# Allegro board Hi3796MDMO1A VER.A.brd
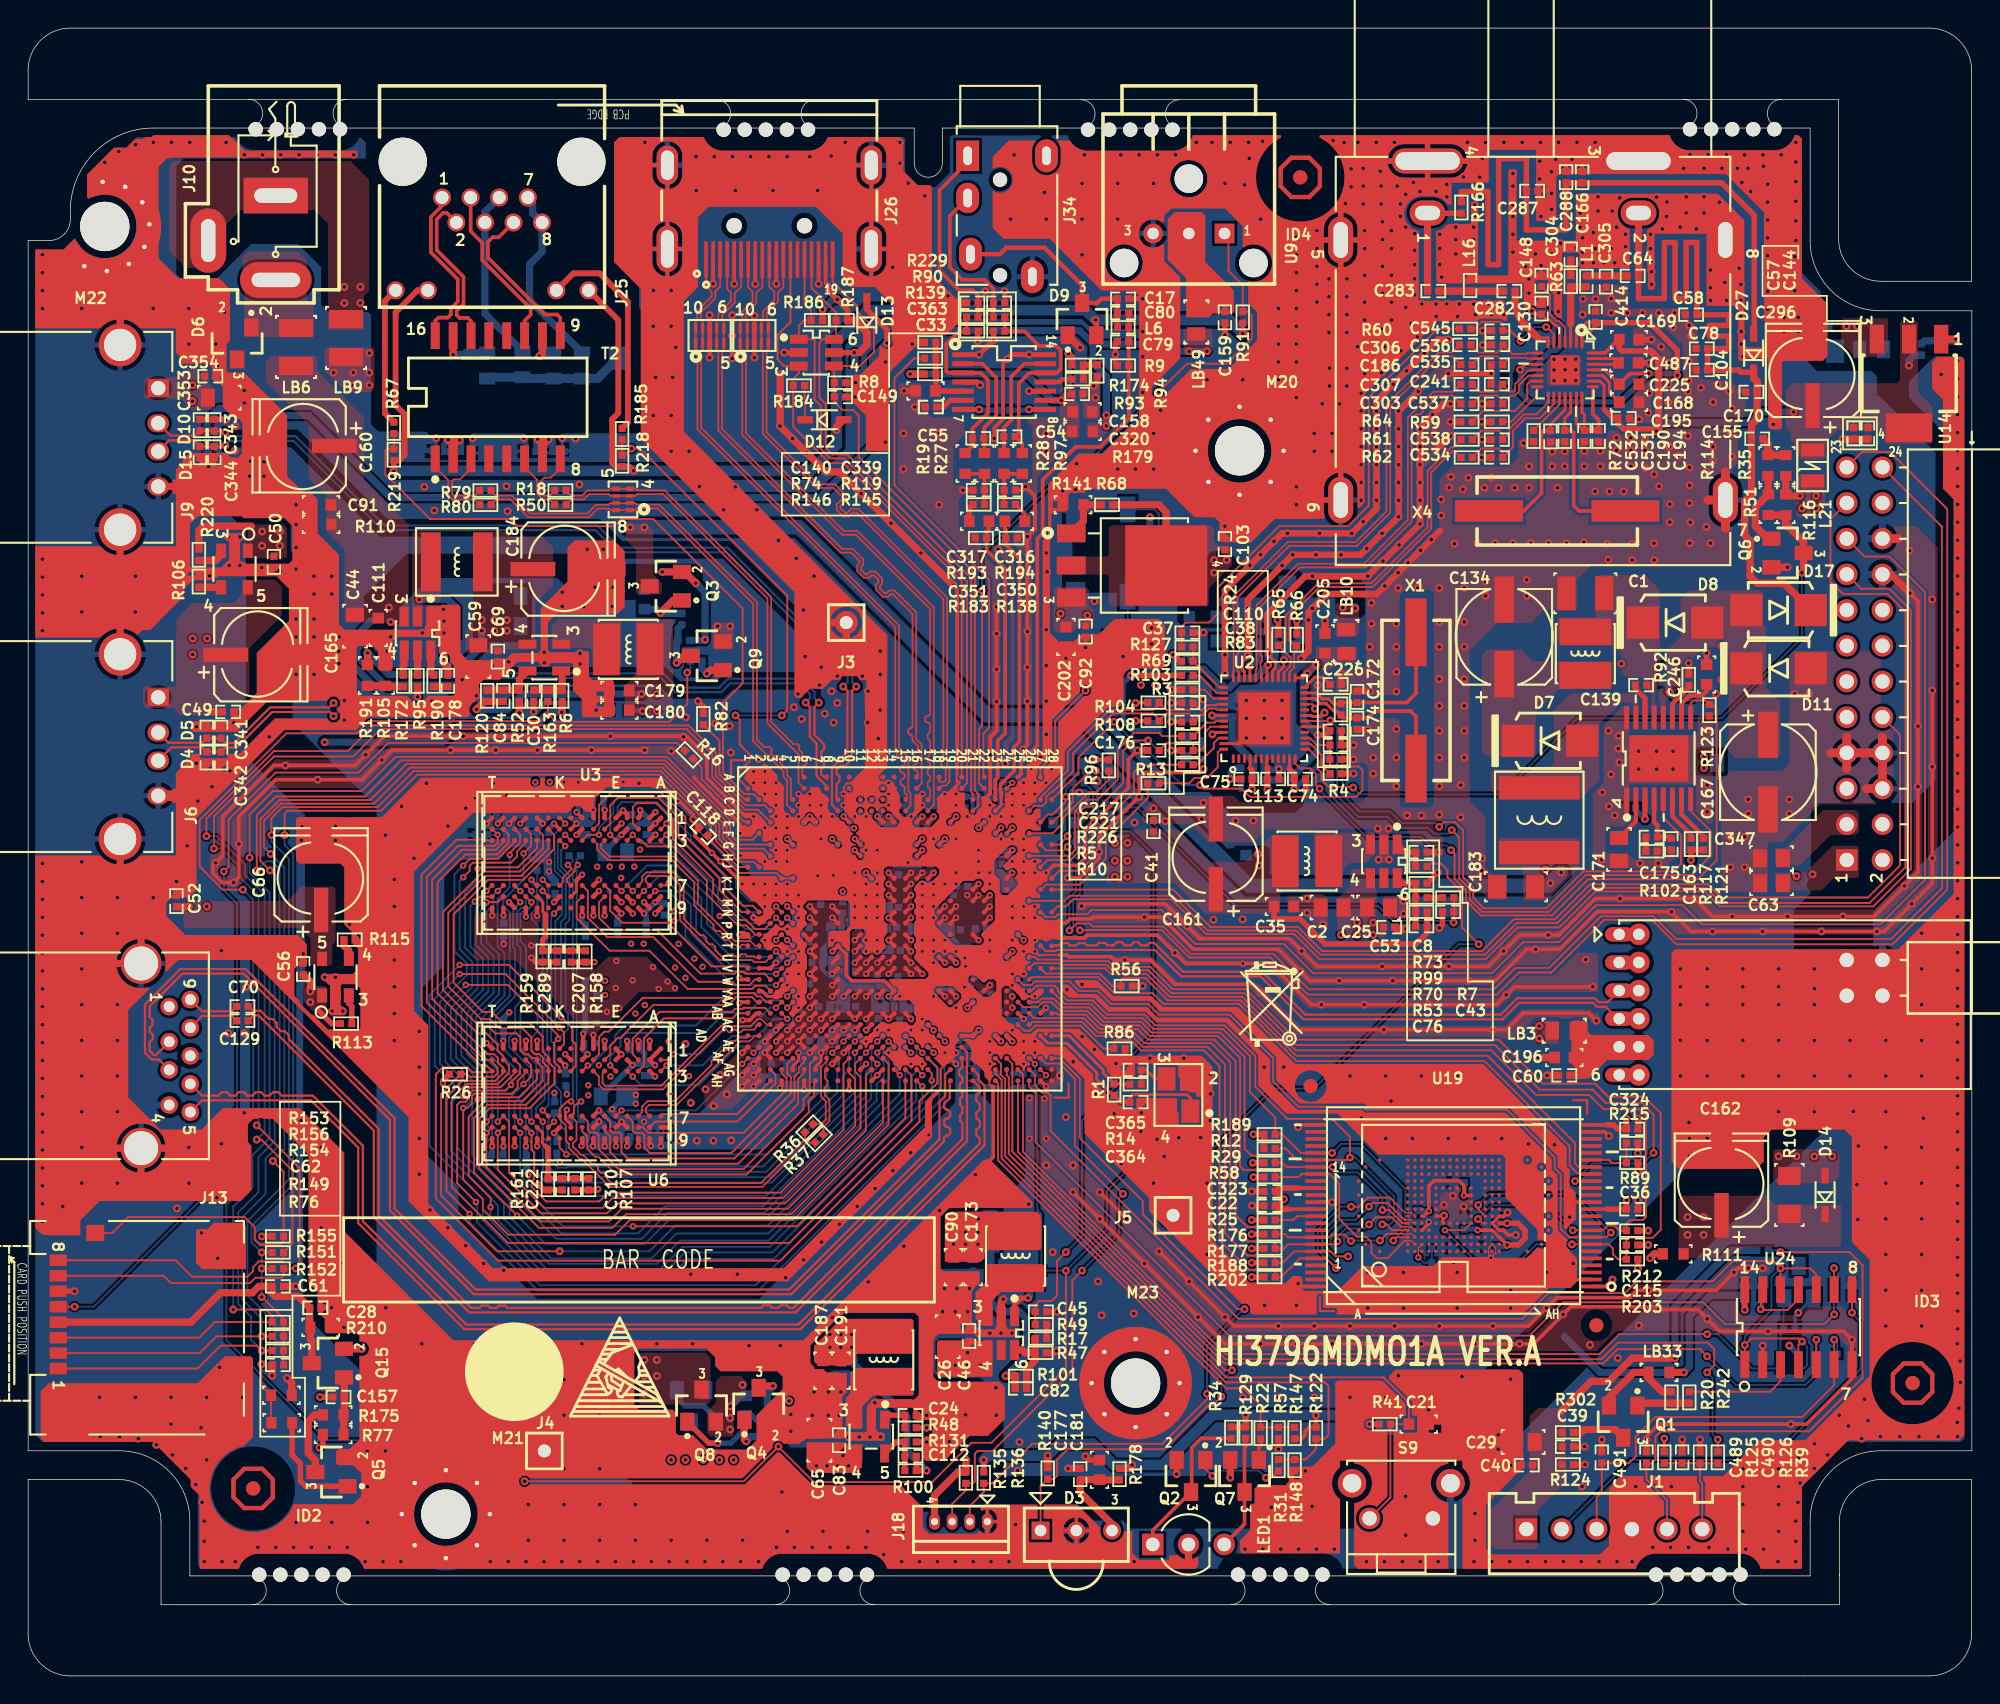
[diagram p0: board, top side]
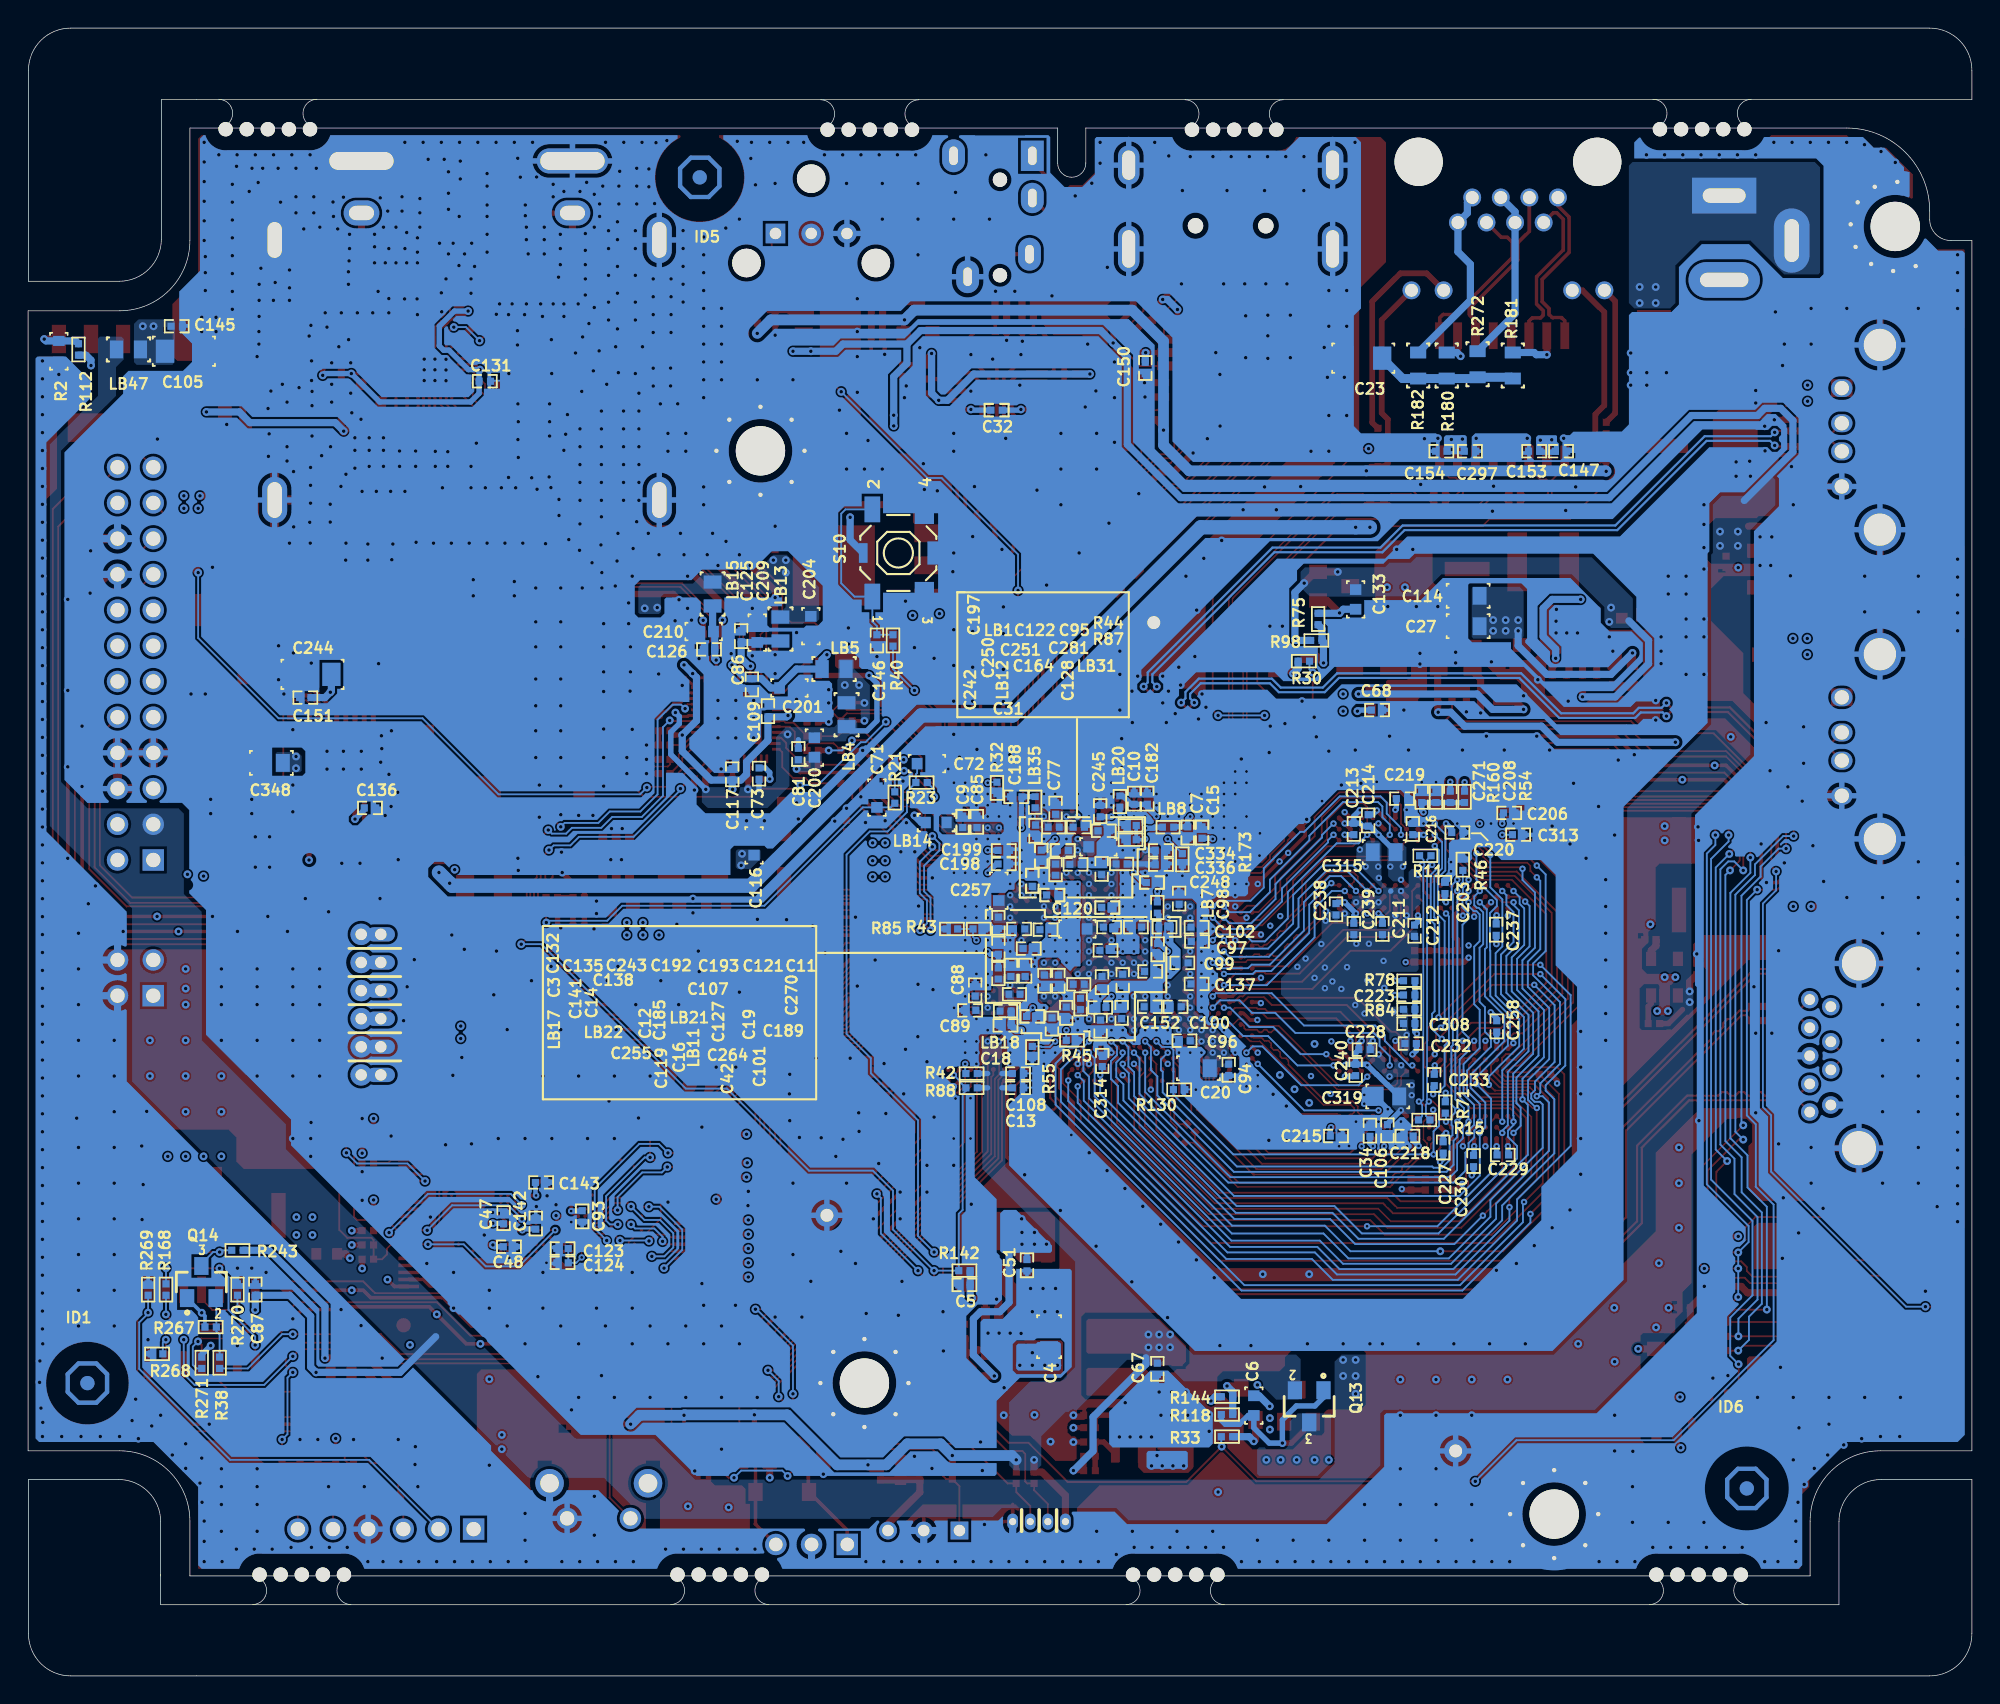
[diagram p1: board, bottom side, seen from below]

Outline 138.2 x 117.22 mm; copper layers: TOP, GND02, POWER03, BOTTOM. Coordinates in mm from the lower left corner of the outline.
Outline path: 128.78,7.11 128.78,10.97 arc(129.66,13.09) 131.78,13.97 138.18,13.97 138.18,3 arc(137.3,0.88) 135.18,0 3,0 arc(0.88,0.88) 0,3 0,13.97 6.45,13.97 arc(8.57,13.09) 9.45,10.97 9.45,5.06 128.78,5.06 128.78,7.24 ; 0,114.22 arc(0.88,116.34) 3,117.22 135.18,117.22 arc(137.3,116.34) 138.18,114.22 138.18,99.21 131.72,99.21 arc(129.61,100.09) 128.73,102.21 128.73,112.14 0,112.14 0,114.22 ; 0,102.11 0,16.01 6.5,16.01 arc(10.04,14.55) 11.5,11.01 11.5,7.11 126.7,7.11 126.7,11.01 arc(128.16,14.55) 131.7,16.01 138.2,16.01 138.2,97.11 131.7,97.11 arc(128.16,98.58) 126.7,102.11 126.7,110.11 65,110.11 65,107.61 arc(64,106.61) 63,107.61 63,110.11 8.9,110.11 arc(4.73,108.38) 3,104.21 3,103.61 arc(2.56,102.55) 1.5,102.11 0,102.11

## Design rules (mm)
constraint set DEFAULT: min track width 0.127
net group $7N2063: nets $7N2063 USB_BOOT
net group $8N1816: nets $8N1816 DDR_CLK1P
net group $8N1817: nets $8N1817 DDR_CLK1N
net group $22N979: nets $22N979 SIM0_DET
net group $22N1011: nets $22N1011 SIM0_DATA
net group DIFFPAIR8: nets DDR_DQS0N DDR_DQS0P
net group DIFFPAIR9: nets DDR_DQS1N DDR_DQS1P
net group DIFFPAIR10: nets DDR_DQS2N DDR_DQS2P
net group DIFFPAIR11: nets DDR_DQS3N DDR_DQS3P
net group DIFFPAIR21: nets $17N178 $17N179
net group DIFFPAIR22: nets $17N175 $17N176
net group DIFFPAIR24: nets USB3_TXN USB3_TXP
net group DIFFPAIR25: nets 3136_QOUT_N 3136_QOUT_P
net group DIFFPAIR26: nets 3136_IOUT_N 3136_IOUT_P
net group DIFFPAIR28: nets $21N333 $21N334
net group DIFFPAIR29: nets $21N336 $21N337
net group DIFFPAIR30: nets $17N281 $17N285
net group DIFFPAIR31: nets $17N276 $17N279
net group 01: nets MUTE_CTRL
net group 02: nets STANDBY_PWROFF
net group $5N541: nets $5N541
net group $5N592: nets $5N592
net group $15N771: nets $15N771 IR_IN UART0_RXD UART0_TXD
net group DDR: nets DDR_ADDR0 DDR_ADDR1 DDR_ADDR2 DDR_ADDR3 DDR_ADDR4 DDR_ADDR5 DDR_ADDR6 DDR_ADDR7 DDR_ADDR8 DDR_ADDR9 DDR_ADDR10 DDR_ADDR11 DDR_ADDR12 DDR_ADDR13 DDR_ADDR14 DDR_ADDR15 DDR_BA0 DDR_BA1 DDR_BA2 DDR_CASN DDR_CKE DDR_CSN DDR_DM0 DDR_DM1 DDR_DM2 DDR_DM3 DDR_DQ0 DDR_DQ1 DDR_DQ2 DDR_DQ3 DDR_DQ4 DDR_DQ5 DDR_DQ6 DDR_DQ7 DDR_DQ8 DDR_DQ9 DDR_DQ10 DDR_DQ11 DDR_DQ12 DDR_DQ13 DDR_DQ14 DDR_DQ15 DDR_DQ16 DDR_DQ17 DDR_DQ18 DDR_DQ19 DDR_DQ20 DDR_DQ21 DDR_DQ22 DDR_DQ23 DDR_DQ24 DDR_DQ25 DDR_DQ26 DDR_DQ27 DDR_DQ28 DDR_DQ29 DDR_DQ30 DDR_DQ31 DDR_ODT DDR_RASN DDR_RESETN DDR_WEN
net group DIFF90: nets USB0_DM USB0_DP USB1_DM USB1_DP
net group PHY: nets RX+_PHY0 RX-_PHY0 TX+_PHY0 TX-_PHY0
net group POWER: nets 1V2_DVDD_S 12V0_MOS ADAC_VOUTL ADAC_VOUTR CVBS
net group USB: nets $14N652 $14N653 USB2_DM USB2_DP USB3_DM USB3_DP USB3_RXN USB3_RXP

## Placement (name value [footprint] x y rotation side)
C1  4.7UF  [SC1210]  110.72 77.01 180 top
C2  10UF  [SC0805]  92.71 54.66 180 top
C3  1UF  [SC0402]  69.22 51.74 90 bottom
C4  10UF  [SC0805]  65.61 24.13 90 bottom
C5  220NF  [SC0402]  71.63 27.81 0 bottom
C6  220NF  [SC0603]  51.05 19.23 270 bottom
C7  1UF  [SC0402]  55.75 59.99 270 bottom
C8  220NF  [SC0402]  99.06 58.6 0 top
C9  2.2UF  [HSC0402]  71.75 60.76 90 bottom
C10  1UF  [SC0402]  59.56 62.41 90 bottom
C11  1UF  [SC0402]  57.4 53.26 180 bottom
C12  1UF  [SC0402]  65.94 49.45 270 bottom
C13  1UF  [SC0402]  67.82 41.83 180 bottom
C14  1UF  [SC0402]  67.31 50.16 90 bottom
C15  2.2UF  [HSC0402]  54.74 59.99 90 bottom
C16  1UF  [SC0402]  64.39 47.17 270 bottom
C17  180PF  [SC0402]  77.85 97.97 0 top
C18  1UF  [SC0402]  68.71 46.28 0 bottom
C19  470NF  [SC0402]  60.38 49.5 270 bottom
C20  10UF  [SC0805]  54.99 43.23 0 bottom
C21  100NF  [SC0603]  98.87 17.91 0 top
C22  2.2UF  [HSC0402]  88.27 33.45 180 top
C23  1NF  [SC1206]  43.27 93.74 0 bottom
C24  220NF  [SC0402]  62.74 18.54 0 top
C25  10UF  [SC0805]  96.01 54.66 0 top
C26  10UF/NC  [SC0805]  65.38 24.13 90 top
C27  10UF/NC  [SC0805]  35.81 74.68 0 bottom
C28  2.2UF  [HSC0402]  20.42 26.19 0 top
C29  10UF  [SC0805]  106.3 16.64 180 top
C30  220NF  [SC0402]  35.94 69.72 270 top
C31  2.2UF  [HSC0402]  65.38 55.55 180 bottom
C32  330N  [HSC0402]  69.34 90.04 0 bottom
C33  330N  [HSC0402]  64.19 90.27 0 top
C34  100NF  [SC0402]  42.8 38.79 90 bottom
C35  10UF  [SC0603]  89.28 54.74 0 top
C36  1UF/NC  [SC0402]  114.05 33.2 0 top
C37  100NF  [SC0402]  82.42 74.22 0 top
C38  100NF  [SC0402]  92.96 66.22 0 top
C39  100NF  [SC0402]  109.47 16.31 0 top
C40  100NF  [SC0402]  106.55 14.99 180 top
C41  100NF  [SC0402]  80.01 60.45 90 top
C42  100NF  [SC0402]  61.95 46.25 270 bottom
C43  100NF/NC  [SC0402]  100.97 54.36 180 top
C44  10UF  [SC0805]  23.24 74.68 270 top
C45  100NF/NC  [SC0402]  72.01 25.91 0 top
C46  100NF  [SC0402]  66.9 24.18 90 top
C47  100NF  [SC0402]  104.39 32.56 90 bottom
C48  100NF  [SC0402]  104.01 30.53 180 bottom
C49  100NF  [SC0402]  14.22 68.58 0 top
C50  100NF  [SC0402]  17.48 79.25 270 top
C51  100NF  [SC0402]  67.18 29.21 270 bottom
C52  100NF  [SC0402]  10.54 55.12 90 top
C53  100NF  [SC0402]  96.77 53.26 0 top
C54  47PF  [SC0402]  69.77 88.16 180 top
C55  47PF  [SC0402]  67.55 88.04 180 top
C56  100NF  [SC0402]  19.56 50.29 90 top
C57  10NF  [HSC0402]  129.79 88.39 270 top
C58  39PF/NC  [SC0402]  118.24 96.84 180 top
C59  10UF  [SC0805]  32 72.52 270 top
C60  100NF  [SC0402]  109.22 42.72 180 top
C61  100NF  [SC0402]  17.75 27.71 0 top
C62  100NF  [SC0402]  17.75 22.12 180 top
C63  10UF  [SC0805]  123.95 56.39 180 top
C64  39PF  [SC0402]  114.09 99.59 180 top
C65  10UF  [SC0805]  56.26 16.76 90 top
C66  100UF  [SAC6666]  20.83 56.98 90 top
C67  100NF  [SC0402]  57.91 21.84 270 bottom
C68  100NF  [SC0402]  42.29 68.71 180 bottom
C69  100NF  [SC0402]  33.4 72.52 270 top
C70  100NF  [SC0402]  15.24 47.62 0 top
C71  2.2UF  [SC0603]  77.85 62.48 90 bottom
C72  2.2UF  [SC0603]  74.3 64.9 180 bottom
C73  100NF  [SC0402]  86.23 64.19 90 bottom
C74  100NF  [SC0402]  90.42 63.8 0 top
C75  100NF  [SC0402]  86.61 63.8 180 top
C76  22PF  [SC0402]  99.06 53.34 0 top
C77  1UF  [SC0402]  65.15 61.7 90 bottom
C78  39PF  [SC0402]  119 94.42 180 top
C79  180PF  [SC0402]  77.85 94.92 180 top
C80  100PF  [SC0402]  77.85 96.95 180 top
C81  100NF  [SC0402]  83.44 65.58 270 bottom
C82  22PF  [SC0402]  70.59 20.45 180 top
C83  100NF  [SC0402]  57.66 16.76 90 top
C84  22PF  [SC0402]  33.78 69.72 270 top
C85  100NF  [SC0402]  70.74 60.76 90 bottom
C86  100NF  [SC0402]  86.74 70.54 270 bottom
C87  100NF  [SC0402]  122.05 27.48 270 bottom
C88  100NF  [SC0402]  70.87 48.77 90 bottom
C89  100NF  [SC0402]  71.22 47.35 0 bottom
C90  10UF  [SC0603]  65.79 29.08 270 top
C91  100NF  [SC0603]  20.83 83.31 180 top
C92  100NF  [SC0402]  75.18 74.3 270 top
C93  100NF  [SC0402]  98.81 32.69 270 bottom
C94  1UF  [SC0402]  52.84 43.12 270 bottom
C95  100NF  [SC0402]  61.72 60.12 180 bottom
C96  1UF  [SC0402]  55.98 45.19 0 bottom
C97  470NF  [SC0402]  55.09 52.25 180 bottom
C98  100NF  [SC0402]  56.36 55.3 90 bottom
C99  100NF  [SC0402]  56.13 50.72 0 bottom
C100  470NF  [SC0402]  56.62 47.6 0 bottom
C101  100NF  [SC0402]  60.45 47.17 90 bottom
C102  100NF  [SC0402]  55.12 53.26 180 bottom
C103  100NF  [SC0402]  85.09 80.52 90 top
C104  39PF/NC  [SC0402]  119 92.9 180 top
C105  10UF  [SC1206]  127.13 94.23 180 bottom
C106  100NF  [SC0402]  41.55 38.81 270 bottom
C107  100NF  [SC0402]  61.59 51.61 180 bottom
C108  100NF  [SC0402]  67.82 42.85 180 bottom
C109  100NF  [SC0402]  85.6 68.63 90 bottom
C110  100NF  [SC0402]  92.96 67.23 0 top
C111  100NF  [SC0603]  24.89 74.55 270 top
C112  22PF  [SC0402]  62.74 15.62 0 top
C113  100NF  [SC0402]  88.52 63.8 0 top
C114  10UF  [SC0805]  35.81 76.83 0 bottom
C115  1NF/NC  [SC0402]  114.05 30.66 0 top
C116  10UF  [SC0603]  86.59 59.08 90 bottom
C117  100NF  [SC0402]  88.14 64.14 90 bottom
C118  2.2UF  [HSC0402]  48.01 60.07 315 top
C119  100NF  [SC0402]  65.41 46.41 270 bottom
C120  2.2UF  [HSC0402]  61.47 54.66 180 bottom
C121  100NF  [SC0402]  59.44 53.26 0 bottom
C122  100NF  [SC0402]  63.5 60.38 180 bottom
C123  100NF  [SC0402]  100.2 30.4 0 bottom
C124  100NF  [SC0402]  100.2 29.39 0 bottom
C125  100NF  [SC0402]  87.5 73.96 90 bottom
C126  100NF  [SC0402]  89.79 73.02 0 bottom
C127  100NF  [SC0402]  61.85 49.35 270 bottom
C128  100NF  [SC0402]  61.87 57.4 90 bottom
C129  100NF  [SC0402]  15.24 46.61 0 top
C130  100NF/NC  [SC0402]  107.6 97.27 90 top
C131  100NF  [SC0402]  105.73 92.1 180 bottom
C132  1UF  [SC0402]  69.22 53.57 270 bottom
C133  1UF  [SC0603]  43.81 76.58 270 bottom
C134  47UF  [SCAPC2-0606]  104.95 73.91 90 top
C135  100NF  [SC0402]  67.74 53.14 0 bottom
C136  100NF  [SC0402]  113.89 61.75 180 bottom
C137  100NF  [SC0402]  55.12 49.23 180 bottom
C138  100NF  [SC0402]  67.06 51.74 180 bottom
C139  100NF  [SC0402]  114.68 70.48 0 top
C140  1NF  [SC0402]  67.13 97.68 180 top
C141  10NF  [SC0402]  68.33 50.16 90 bottom
C142  100NF/NC  [SC0402]  102.11 32.18 90 bottom
C143  100NF/NC  [SC0402]  101.73 35.1 180 bottom
C144  100NF  [SC0402]  130.81 88.39 270 top
C145  100NF  [SC0402]  127.64 96.01 180 bottom
C146  100NF  [SC0402]  77.85 73.66 270 bottom
C147  10NF/NC  [SC0402]  29.21 87.12 180 bottom
C148  22PF  [SC0402]  107.6 99.25 90 top
C149  100NF  [SC0402]  57.73 90.98 0 top
C150  100NF  [SC0402]  58.77 93.04 270 bottom
C151  100NF  [SC0402]  118.49 69.6 0 bottom
C152  1UF  [SC0402]  58.45 47.6 180 bottom
C153  100NF  [SC0402]  31.11 87.12 0 bottom
C154  100NF  [SC0402]  37.72 87.12 0 bottom
C155  100NF  [SC0402]  122.94 88.01 180 top
C157  1UF  [SC0402]  22.07 19.84 0 top
C158  100NF  [SC0402]  74.59 91.2 0 top
C159  100NF  [SC0402]  85.09 96.65 270 top
C160  100UF  [SAC6666]  19.27 87.5 180 top
C161  100UF  [SAC6666]  84.45 58.46 90 top
C162  100UF/NC  [SAC6666]  120.4 35.27 90 top
C163  470PF  [SC0402]  116.83 59.17 90 top
C164  10NF  [SC0402]  63.73 57.73 180 bottom
C165  100UF  [SAC6666]  16.55 72.64 0 top
C166  1NF  [SC0402]  110.49 106.62 90 top
C167  47UF/NC  [SCAPC2-0606]  123.7 64.29 270 top
C168  1NF  [SC0603]  113.82 90.62 180 top
C169  1NF/NC  [SC0603]  113.82 95.06 180 top
C170  1NF  [SC0402]  122.53 91.34 180 top
C171  220NF  [SC0805]  113.12 58.79 90 top
C172  30PF  [SC0402]  94.49 69.65 90 top
C173  10UF  [SC0603]  67.18 29.08 270 top
C174  30PF  [SC0402]  94.49 67.74 270 top
C175  47NF  [SC0402]  115.43 59.68 0 top
C176  1PF/NC  [SC0402]  80.01 65.84 180 top
C177  100NF  [SC0402]  74.8 14.35 90 top
C178  1UF  [SC0402]  29.84 70.79 90 top
C179  10UF  [SC0603]  42.04 70.1 180 top
C180  10UF  [SC0603]  42.04 68.71 180 top
C181  10UF  [SC0603]  76.17 14.66 90 top
C182  10NF  [SC0402]  58.62 62.41 90 bottom
C183  10UF  [SC1206]  105.79 56.13 180 top
C184  100UF  [SAC6666]  38.39 78.74 0 top
C185  10NF  [SC0402]  64.95 49.45 270 bottom
C186  100NF  [SC0402]  102.27 93.28 180 top
C187  10UF  [SC0603]  56.52 21.72 270 top
C188  1UF  [SC0402]  67.94 62.53 0 bottom
C189  1UF  [SC0402]  58.42 50.11 180 bottom
C190  100NF/NC  [SC0402]  110.65 88.2 270 top
C191  10UF  [SC0603]  57.78 21.72 270 top
C192  10UF  [SC0603]  63.6 53.14 0 bottom
C193  1UF  [SC0402]  61.34 53.26 180 bottom
C194  100NF  [SC0402]  111.67 88.2 270 top
C195  100NF  [SC0402]  113.44 89.47 180 top
C196  10UF  [SC0603]  109.22 43.99 180 top
C197  100NF  [SC0402]  66.57 60.12 270 bottom
C198  100NF  [SC0402]  68.83 57.76 180 bottom
C199  100NF  [SC0402]  68.83 58.72 180 bottom
C200  10UF  [SC0603]  82.3 66.04 270 bottom
C201  10UF  [SC0603]  84.07 70.28 180 bottom
C202  10UF  [SC0603]  73.79 73.91 270 top
C203  100NF  [SC0402]  37.47 56.06 90 bottom
C204  10UF  [SC0603]  82.55 74.68 270 bottom
C205  10UF  [SC0603]  92.2 73.46 90 top
C206  100NF  [SC0402]  32.89 61.39 180 bottom
C207  100NF  [SC0402]  38.61 51.18 90 top
C208  100NF  [SC0402]  37.08 62.53 270 bottom
C209  10UF  [SC0603]  86.36 74.22 90 bottom
C210  10UF  [SC0603]  90.17 74.3 0 bottom
C211  100NF  [SC0402]  41.91 53.14 270 bottom
C212  100NF  [SC0402]  39.62 53.01 270 bottom
C213  100NF  [SC0402]  43.94 60.25 270 bottom
C214  100NF  [SC0402]  42.92 60.86 90 bottom
C215  100NF  [SC0402]  45.21 38.4 180 bottom
C216  100NF  [SC0402]  39.75 60.25 90 bottom
C217  33PF/NC  [SC0402]  82.42 69.22 180 top
C218  100NF  [SC0402]  40.13 38.4 0 bottom
C219  100NF  [SC0402]  40.51 62.41 180 bottom
C220  100NF  [SC0402]  36.58 59.99 180 bottom
C221  33PF/NC  [SC0402]  82.42 67.87 180 top
C222  100NF  [SC0402]  37.97 34.98 90 top
C223  100NF  [SC0402]  40.01 48.44 180 bottom
C225  1NF/NC  [SC0603]  113.82 91.89 180 top
C226  10PF  [SC0402]  92.96 70.54 0 top
C227  100NF  [SC0402]  37.59 37.59 270 bottom
C228  100NF  [SC0402]  43.18 44.55 180 bottom
C229  100NF  [SC0402]  33.35 37.06 180 bottom
C230  100NF  [SC0402]  35.43 36.63 270 bottom
C232  100NF  [SC0402]  39.9 44.98 0 bottom
C233  100NF  [SC0402]  38.23 42.39 270 bottom
C237  100NF  [SC0402]  33.82 53.09 270 bottom
C238  100NF  [SC0402]  45.21 54.53 270 bottom
C239  100NF  [SC0402]  43.94 53.14 270 bottom
C240  100NF  [SC0402]  43.81 43.1 270 bottom
C241  10PF  [SC0402]  104.43 91.89 180 top
C242  2.2UF  [HSC0402]  66.8 56.57 90 bottom
C243  470NF  [SC0402]  65.86 53.09 180 bottom
C244  1UF/NC  [SC1206]  117.98 71.25 0 bottom
C245  100NF  [SC0402]  61.98 61.52 90 bottom
C246  22NF  [SC0603]  119.34 71.24 90 top
C248  2.2UF  [HSC0402]  58.29 56.44 180 bottom
C250  2.2UF  [HSC0402]  66.17 58.34 90 bottom
C251  2.2UF  [HSC0402]  64.64 58.72 0 bottom
C255  2.2UF  [HSC0402]  66.8 46.91 0 bottom
C257  10UF  [SC0603]  69.19 55.85 90 bottom
C258  100NF  [SC0402]  33.78 46.2 90 bottom
C264  10NF  [SC0402]  61.98 47.55 0 bottom
C270  10NF  [SC0402]  57.89 51.69 270 bottom
C271  1UF  [SC0402]  39.12 62.53 90 bottom
C281  10UF  [SC0603]  62.1 58.98 180 bottom
C282  47PF  [SC0402]  105.32 98.51 0 top
C283  47PF  [SC0402]  99.9 98.51 0 top
C287  2.2NF  [SC0402]  106.93 105.64 0 top
C288  1NF  [SC0402]  109.35 106.62 90 top
C289  1UF  [SC0402]  37.59 51.18 270 top
C296  220UF  [SAC6666]  126.87 92.87 90 top
C297  10NF/NC  [SC0402]  35.69 87.12 180 bottom
C303  100NF  [SC0402]  102.27 90.49 180 top
C304  100NF/NC  [SC0402]  109.68 101.12 270 top
C305  100NF/NC  [SC0402]  112.19 99.19 90 top
C306  100NF  [SC0402]  102.17 94.68 180 top
C307  100NF  [SC0402]  102.27 91.89 180 top
C308  1UF  [SC0402]  40.01 46.41 0 bottom
C310  1UF  [SC0402]  38.86 34.98 270 top
C313  1NF  [SC0402]  32.26 59.84 180 bottom
C314  1NF  [SC0402]  61.83 43.75 90 bottom
C315  10UF  [SC0805]  41.78 58.6 0 bottom
C316  680PF  [SC0402]  69.8 84.35 0 top
C317  680PF  [SC0402]  67.59 84.35 180 top
C319  10UF  [SC0805]  41.53 41.22 0 bottom
C320  10UF  [SC0603]  74.97 89.93 0 top
C323  100NF  [SC0402]  88.27 34.47 180 top
C324  100NF  [SC0402]  114.05 38.91 0 top
C334  1UF  [SC0402]  57.66 58.72 180 bottom
C336  10NF  [SC0402]  57.66 57.71 180 bottom
C339  1NF  [SC0402]  69.04 97.68 0 top
C341  3PF  [SC0402]  13.72 67.11 270 top
C342  3PF  [SC0402]  13.72 65.33 90 top
C343  3PF  [SC0402]  13.23 88.98 270 top
C344  3PF  [SC0402]  13.23 87.05 90 top
C347  10UF  [SC0805]  123.95 58.17 180 top
C348  10UF  [SC0805]  120.9 64.95 0 bottom
C350  2.2UF  [SC0603]  70.15 82.14 180 top
C351  2.2UF  [SC0603]  67.61 82.14 180 top
C353  10UF  [SC0805]  13.59 90.93 0 top
C354  100NF  [SC0402]  12.95 92.46 0 top
C363  10UF/NC  [SC0603]  63.8 91.41 180 top
C364  30PF  [SC0402]  78.74 40.82 0 top
C365  30PF  [SC0402]  78.74 43.1 180 top
C414  10NF  [SC0402]  111.45 96.67 90 top
C487  1UF  [SC0603]  113.77 93.41 180 top
C489  100PF  [SC0402]  115.06 15.54 90 top
C490  100PF  [SC0402]  117.6 15.54 90 top
C491  100PF  [SC0402]  111.89 15.54 90 top
C531  27PF  [SC0402]  109.25 88.2 270 top
C532  27PF  [SC0402]  108.24 88.18 270 top
C534  10PF  [SC0402]  104.43 86.68 180 top
C535  10PF  [SC0402]  104.43 93.28 180 top
C536  10PF  [SC0402]  104.46 94.68 180 top
C537  10PF  [SC0402]  104.43 90.49 180 top
C538  10PF  [SC0402]  104.43 87.95 180 top
C545  100PF  [SC0402]  104.46 95.7 180 top
D3  IR  [SEN3-100C]  74.52 10.34 0 top
D4  NC  [SC0402]  12.7 65.33 270 top
D5  NC  [SC0402]  12.7 67.11 90 top
D6  D2-3_D  [SOT23]  14.86 94.79 180 top
D7  DIODE  [SD1714A]  108.2 66.52 180 top
D8  DIODE  [SD1714A]  117.09 74.93 180 top
D9  D2-3_A  [SOT23]  74.93 96.52 0 top
D10  NC  [SC0402]  12.22 88.98 90 top
D11  DIODE  [SD1714A]  124.46 71.68 180 top
D12  D_A  [HSOD323A]  56.61 89.36 180 top
D13  D_A  [HSOD323A]  59.63 96.44 270 top
D14  NC  [HSOD323A]  127.76 34.21 270 top
D15  NC  [SC0402]  12.22 87.05 270 top
D17  DIODE  [SD1714A]  124.46 75.82 0 top
D27  D_A  [HSOD323A]  122.68 94.11 270 top
ID1  PCB_MARKPOINT_A  [ID-BOARD]  133.99 20.83 180 bottom
ID2  PCB_MARKPOINT_A  [ID-BOARD]  16 13.34 0 top
ID3  PCB_MARKPOINT_A  [ID-BOARD]  133.99 20.83 0 top
ID4  PCB_MARKPOINT_A  [ID-BOARD]  90.45 106.6 0 top
ID5  PCB_MARKPOINT_A  [ID-BOARD]  90.45 106.6 180 bottom
ID6  PCB_MARKPOINT_A  [ID-BOARD]  16 13.34 180 bottom
J1  TJC3_6A_34HW  [SIP-6P-100]  112.78 10.44 180 top
J3  NC  [SIP-1P]  58.17 74.93 0 top
J4  NC  [SIP-1P]  36.7 16 270 top
J5  NC  [SIP-1P]  81.41 32.77 270 top
J6  292303_1  [USB4-1415]  9.25 69.61 270 top
J7  D2008_2X12A  [HEAD0212-RF-SUB]  130.57 72.01 90 top
J9  292303_1  [USB4-1415]  9.25 91.61 270 top
J10  DC2026_00  [PWC0103-M-N]  17.61 105.31 90 top
J12  USB3_ATYPE  [USB3_0_9P_DIP_MAINSUPER]  10.03 47.61 270 top
J13  5031820832  [SDC10-1415]  7.75 24.77 270 top
J14  /NC  [HEAD0202-RF]  130.57 49.66 90 top
J16  -  [JTDA18250]  107 92.9 270 top
J18  SDW12501_4A_HW  [WBC0104-49T]  68.2 10.97 180 top
J25  406533_1  [MJ8-RLY]  29.43 105.17 0 top
J26  0  [WBC0119-20R-A]  52.7 105.91 180 top
J34  8967_3506ADT_M_A  [VAF6-1107]  66.8 108.14 270 top
L1  3.3NH  [SL0402]  110.79 99.21 270 top
L2  3.3UH  [SWPA4030S]  42.67 73.02 0 top
L3  3.3UH  [SWPA4030S]  70.21 29.87 90 top
L4  3.3UH  [SWPA4030S]  90.93 57.96 180 top
L5  3.3UH  [SWPA4030S]  60.83 22.48 90 top
L6  220NH  [SL0402]  77.85 95.94 180 top
L7  22UH/2A  [L6X6X4_5]  107.44 60.87 90 top
L8  4.7UH  [SWPA5040S]  30.48 79.25 0 top
L9  1UH  [SWPA4020S]  110.72 72.72 90 top
L16  NC/3.3NH  [SL0402]  102.52 98.91 270 top
L21  4.7UH/NC  [HSL1007]  126.87 86.11 90 top
LB1  BLM15BD601SN1D  [SL0402]  65.28 60.38 0 bottom
LB3  MGLB2012_220T_LF  [SL0805]  109.22 45.9 0 top
LB4  MGLB2012_220T_LF  [SL0805]  80.01 68.38 270 bottom
LB5  MGLB2012_220T_LF  [SL0805]  80.9 71.63 0 bottom
LB6  FCFBMH3225HM601NT  [SL1210]  19.05 94.54 270 top
LB7  BLM15HB221SN1D  [SL0402]  57.91 54.66 90 bottom
LB8  BLM15HB221SN1D  [SL0402]  57.15 60.38 0 bottom
LB9  FCFBMH3225HM601NT  [SL1210]  22.61 95.17 270 top
LB10  MGLB2012_220T_LF  [SL0805]  93.73 73.58 270 top
LB11  BLM15HB221SN1D  [SL0402]  63.37 47.8 270 bottom
LB12  BLM15BD601SN1D  [SL0402]  65.15 57.35 270 bottom
LB13  MGLB2012_220T_LF  [SL0805]  84.71 74.47 270 bottom
LB14  MGLB1608_030T_LF  [SL0603]  73.63 60.71 180 bottom
LB15  MGLB2012_220T_LF  [SL0805]  89.53 76.96 270 bottom
LB17  BLM15HB221SN1D  [SL0402]  69.22 49.96 90 bottom
LB18  BLM15HB221SN1D  [SL0402]  68.71 47.29 180 bottom
LB20  BLM15HB221SN1D  [SL0402]  60.58 62.2 90 bottom
LB21  BLM15HB221SN1D  [SL0402]  63.5 49.2 0 bottom
LB22  BLM15HB221SN1D  [SL0402]  68.07 48.49 180 bottom
LB31  BLM15HB221SN1D  [SL0402]  60.45 57.76 180 bottom
LB33  MGLB1608_030T_LF  [SL0603]  115.95 21.59 180 top
LB35  BLM15HB221SN1D  [SL0402]  66.6 62.15 90 bottom
LB47  MGLB2012_220T_LF  [SL0805]  131.06 94.36 180 bottom
LB49  MGLB2012_220T_LF  [SL0805]  83.06 96.32 90 top
LED1  NC  [LED3C-100C]  79.96 9.35 0 top
M20  138MIL_STAR_HOLE_APPLY_TO_M3  [HOLE138-8STAR]  86.13 87.15 0 top
M21  138MIL_STAR_HOLE_APPLY_TO_M3  [HOLE138-8STAR]  29.7 11.51 0 top
M22  138MIL_STAR_HOLE_APPLY_TO_M3  [HOLE138-8STAR#2]  5.45 103.11 45 top
M23  138MIL_STAR_HOLE_APPLY_TO_M3  [HOLE138-8STAR]  78.74 20.83 0 top
NOREF  -  []  28.54 7.11 90 top
NOREF#2  -  []  0 16.04 0 top
NOREF#3  -  [unnamed#2]  52.45 111.12 180 top
NOREF#4  -  []  2.76 102.8 0 top
NOREF#5  -  [unnamed#2]  19.18 111.16 180 top
NOREF#6  -  []  63 109.15 0 top
NOREF#7  -  []  43.43 29.59 0 top
NOREF#8  -  []  0 18.66 0 top
NOREF#9  -  []  35.08 21.87 0 top
NOREF#10  -  [unnamed#2]  56.64 6.07 0 top
NOREF#11  -  [unnamed#2]  118.75 6.08 0 top
NOREF#12  -  []  90.93 47.89 0 top
NOREF#13  -  []  4.01 107.51 0 top
NOREF#14  -  []  41.38 21.48 0 top
NOREF#15  -  []  -131.43 206.84 0 top
NOREF#16  -  []  109.6 224.71 0 top
NOREF#17  -  [unnamed#2]  78.36 111.12 180 top
NOREF#18  -  [unnamed#2]  89.03 6.08 0 top
NOREF#19  -  [unnamed#2]  19.43 6.07 0 top
NOREF#20  -  []  -100.33 165.61 0 top
NOREF#21  -  []  129.83 97.47 0 top
NOREF#22  -  [unnamed#2]  121.16 111.16 180 top
NOREF#23  -  []  29.46 7.11 90 top
NOREF#24  -  []  128.64 149.64 180 top
Q1  BC856B215  [SOT23]  113.41 18.08 180 top
Q2  NPN-BEC  [SOT23]  82.68 14.22 180 top
Q3  PMOS-GSD  [SOT23]  45.34 77.52 90 top
Q4  NPN-BEC  [SOT23]  51.94 19.35 0 top
Q5  NPN-BEC  [SOT23]  21.56 14.5 90 top
Q6  NPN-BEC  [SOT23]  125.09 79.88 270 top
Q7  NPN-BEC  [SOT23]  86.49 14.22 180 top
Q8  PMOS-GSD  [SOT23]  47.88 19.23 0 top
Q9  NPN-BEC  [SOT23]  48.26 72.57 90 top
Q13  PMOS-GSD  [SOT23]  47.12 19.18 0 bottom
Q14  FETN-GSD  [SOT23]  125.88 28.02 180 bottom
Q15  PMOS-GSD  [SOT23]  21.31 22.25 90 top
R1  1MEG  [SR0402]  77.22 41.71 270 top
R2  249  [SR0603]  136.02 94.23 270 bottom
R3  2K  [SR0402]  82.42 70.15 180 top
R4  2K  [SR0402]  92.96 64.19 0 top
R5  33  [SR0402]  82.42 65.84 0 top
R6  47K  [SR0402]  37.97 69.72 90 top
R7  51K  [SR0402]  100.97 55.37 0 top
R8  47K  [SR0402]  57.73 92 180 top
R9  75  [SR0402]  77.85 93.22 180 top
R10  33  [SR0402]  82.42 64.82 0 top
R11  200  [SR0402]  38.86 58.34 180 bottom
R12  47K  [SR0402]  88.27 37.52 0 top
R13  33  [SR0402]  80.01 63.5 0 top
R14  0  [SR0402]  78.74 42.09 0 top
R15  200  [SR0402]  38.94 39.55 180 bottom
R16  22  [SR0402]  46.99 65.53 315 top
R17  14.7K  [SR0402]  72.01 24 0 top
R18  10  [SR0402]  37.85 84.33 180 top
R19  75K  [SR0603]  66.62 86.25 90 top
R20  47K  [SR0402]  116.84 19.81 270 top
R21  1K  [SR0402]  76.58 62.48 90 bottom
R22  1K  [SR0402]  87.63 17.27 270 top
R23  1K  [SR0402]  74.68 63.55 180 bottom
R24  1MEG  [SR0402]  93.34 68.76 270 top
R25  0/NC  [SR0402]  88.27 32.44 0 top
R26  10K  [SR0402]  30.35 42.8 180 top
R27  5.1K  [SR0603]  68 86.26 90 top
R28  5.1K  [SR0603]  69.39 86.26 270 top
R29  47K  [SR0402]  88.27 36.5 0 top
R30  47K  [SR0402]  47.5 72.19 0 bottom
R31  1K  [SR0402]  88.9 14.99 270 top
R32  12K  [SR0402]  69.32 63.17 90 bottom
R33  47K  [SR0402]  52.96 17.02 180 bottom
R34  1K  [SR0402]  85.55 17.3 270 top
R35  150K  [SR0603]  124.97 86.11 90 top
R36  0  [SR0402]  55.52 38.96 45 top
R37  0  [SR0402]  56.24 38.23 45 top
R38  33  [SR0402]  124.59 22.28 90 bottom
R39  33  [SR0402]  120.14 15.54 270 top
R40  1K  [SR0402]  76.71 73.66 270 bottom
R41  10K  [SR0402]  96.46 17.91 0 top
R42  10K/NC  [SR0402]  71.12 42.85 180 bottom
R43  270  [SR0402]  70.61 53.14 180 bottom
R44  270  [SR0402]  59.82 60.5 180 bottom
R45  240  [SR0402]  63.98 45.21 180 bottom
R46  240  [SR0402]  36.2 57.71 270 bottom
R47  13.7K  [SR0402]  71.98 22.99 0 top
R48  47K  [SR0402]  62.74 17.65 180 top
R49  100K  [SR0402]  72.01 25.02 180 top
R50  10  [SR0402]  37.85 83.31 180 top
R51  19.6K  [SR0603]  123.73 83.32 90 top
R52  100K  [SR0402]  34.92 69.72 270 top
R53  15K  [SR0402]  99.06 54.36 0 top
R54  1K  [SR0402]  36.07 62.53 270 bottom
R55  200  [SR0402]  66.8 44.37 270 bottom
R56  10K  [SR0402]  78.11 49.07 180 top
R57  4.7K/NC  [SR0402]  88.9 17.27 270 top
R58  47K  [SR0402]  88.27 35.48 0 top
R59  2K/NC  [SR0402]  104.43 89.22 180 top
R60  220  [SR0402]  102.17 95.83 0 top
R61  0  [SR0402]  102.28 87.95 180 top
R62  0  [SR0402]  102.28 86.68 180 top
R63  0/NC  [SR0402]  109.68 99.22 90 top
R64  0  [SR0402]  102.27 89.22 180 top
R65  2K  [SR0402]  88.9 73.71 270 top
R66  2K  [SR0402]  90.2 73.71 270 top
R67  330  [SR0402]  26 88.78 270 top
R68  150/NC  [SR0402]  76.71 83.31 0 top
R69  1K  [SR0402]  82.42 72.19 0 top
R70  33K  [SR0402]  99.06 55.37 0 top
R71  240  [SR0402]  37.44 40.44 270 bottom
R72  2K/NC  [SR0402]  107.04 88.2 270 top
R73  20K  [SR0402]  99.06 57.58 180 top
R74  560  [HSR0402]  67.13 96.67 180 top
R75  100K  [SR0402]  46.48 75.18 270 bottom
R76  10K  [SR0603]  18.03 18.01 0 top
R77  10K  [SR0603]  21.69 17.17 0 top
R78  1K  [SR0402]  40.01 49.45 180 bottom
R79  10  [SR0402]  32.51 84.33 180 top
R80  10  [SR0402]  32.51 83.31 180 top
R82  10K  [SR0402]  48.01 68.07 270 top
R83  10K  [SR0402]  92.96 65.2 0 top
R84  1K  [SR0402]  40.01 47.42 0 bottom
R85  270  [SR0402]  72.52 53.14 0 bottom
R86  10K/NC  [SR0402]  77.6 44.63 0 top
R87  270  [SR0402]  59.82 59.49 180 bottom
R88  1K  [SR0402]  71.12 41.83 180 bottom
R89  1K/NC  [SR0402]  114.05 36.5 0 top
R90  1K  [SR0402]  64.14 93.73 0 top
R91  1K  [SR0402]  86.36 96.65 270 top
R92  10K  [SR0402]  118.07 70.86 90 top
R93  0  [SR0402]  74.63 92.25 0 top
R94  2.2K  [SR0402]  76.02 92.86 270 top
R95  100K  [SR0402]  27.69 70.79 90 top
R96  10K/NC  [SR0402]  76.83 64.77 90 top
R97  75K  [SR0603]  70.69 86.25 270 top
R98  4.7K  [SR0402]  46.61 73.66 180 bottom
R99  11.3K  [SR0402]  99.06 56.39 180 top
R100  100K  [SR0402]  62.74 14.61 0 top
R101  14.7K  [SR0402]  70.59 21.34 180 top
R102  4.7K  [SR0402]  115.43 58.67 180 top
R103  2K  [SR0402]  82.42 71.17 180 top
R104  2K  [SR0402]  80.01 69.24 0 top
R105  7.68K  [SR0603]  25.4 71.17 90 top
R106  22K  [SR0402]  12.14 77.85 270 top
R107  1K  [SR0402]  39.88 34.98 270 top
R108  2K  [SR0402]  80.01 67.94 0 top
R109  0  [SR1206]  125.22 34.21 270 top
R110  2K  [SR0603]  20.83 81.91 180 top
R111  2K/NC  [SR0603]  116.97 30.02 180 top
R112  150  [SR0402]  134.62 94.36 270 bottom
R113  10K  [SR0402]  22.61 46.41 180 top
R114  2K  [SR0603]  123.7 86.11 90 top
R115  22K  [SR0402]  22.86 52.37 180 top
R116  2K  [SR0603]  124.97 83.31 90 top
R117  75K  [SR0402]  118.23 59.17 90 top
R118  100K  [SR0402]  52.96 18.59 180 bottom
R119  560  [HSR0402]  69.04 96.67 180 top
R120  150K  [SR0402]  32.64 69.72 270 top
R121  75K  [SR0402]  119.12 59.17 90 top
R122  4.7K/NC  [SR0402]  91.57 17.27 270 top
R123  75K  [SR0402]  119.54 68.7 270 top
R124  10K  [SR0402]  109.47 15.04 180 top
R125  10K  [SR0402]  116.33 15.54 90 top
R126  10K/NC  [SR0402]  118.87 15.54 270 top
R127  4.7K  [SR0402]  82.42 73.2 180 top
R129  1K  [SR0402]  86.56 17.3 270 top
R130  10K/NC  [SR0402]  56.36 41.71 0 bottom
R131  22K  [SR0402]  62.74 16.64 0 top
R135  10K  [SR0402]  66.67 14.1 270 top
R136  10K  [SR0402]  67.94 14.1 90 top
R138  470K  [SR0402]  69.93 80.95 0 top
R139  470K/NC  [SR0402]  64.12 92.61 180 top
R140  10K  [SR0402]  72.49 14.4 90 top
R141  0  [SR0603]  74.3 83.31 180 top
R142  20K  [SR0402]  71.63 28.83 180 bottom
R144  4.7K  [SR0402]  52.96 19.86 180 bottom
R145  100K/NC  [SR0402]  69.04 95.65 180 top
R146  100K/NC  [SR0402]  67.13 95.65 0 top
R147  4.7K  [SR0402]  90.04 17.27 90 top
R148  4.7K  [SR0402]  90.04 14.99 270 top
R149  4.7K  [SR0603]  18.01 19.96 0 top
R151  47K  [SR0402]  17.75 30.12 0 top
R152  47K  [SR0402]  17.75 28.98 0 top
R153  47K  [SR0402]  17.75 25.17 180 top
R154  47K  [SR0402]  17.75 23.14 180 top
R155  47K  [SR0402]  17.75 31.27 0 top
R156  47K  [SR0402]  17.75 24.16 180 top
R158  1K  [SR0402]  39.62 51.18 90 top
R159  1K  [SR0402]  36.58 51.18 270 top
R160  1K  [SR0402]  38.1 62.53 90 bottom
R161  1K  [SR0402]  36.96 34.98 90 top
R163  20K/NC  [SR0402]  36.96 69.72 90 top
R166  NC/0  [SR0402]  101.9 104.46 90 top
R168  75  [SR0402]  128.4 27.48 90 bottom
R172  24.9K  [SR0402]  26.67 70.79 270 top
R173  10K  [SR0402]  56.13 58.09 270 bottom
R174  5.6K  [SR0402]  74.63 93.26 0 top
R175  100  [SR0603]  21.69 18.57 180 top
R176  47K  [SR0402]  88.27 31.42 0 top
R177  47K  [SR0402]  88.27 30.4 0 top
R178  75  [SR0402]  77.6 14.35 270 top
R179  10  [SR0603]  74.97 88.53 180 top
R180  75  [SR0805]  37.34 93.22 90 bottom
R181  75  [SR0805]  32.64 93.22 90 bottom
R182  75  [SR0805]  39.37 93.22 90 bottom
R183  470K  [SR0402]  67.74 80.95 180 top
R184  27K  [SR0402]  54.81 91.79 180 top
R185  330  [SR0402]  42.23 88.35 270 top
R186  2K  [SR0402]  56.08 96.44 0 top
R187  2K  [SR0402]  57.85 96.44 0 top
R188  47K  [SR0402]  88.27 29.39 0 top
R189  47K  [SR0402]  88.27 38.53 0 top
R190  20  [SR0402]  28.83 70.79 270 top
R191  40.2K  [SR0603]  24.13 71.17 90 top
R193  20K  [SR0402]  67.59 83.34 0 top
R194  20K  [SR0402]  69.8 83.34 0 top
R202  47K  [SR0402]  88.27 28.37 0 top
R203  47K  [SR0402]  114.05 29.64 180 top
R210  1K  [SR0603]  20.8 24.79 0 top
R212  10K  [SR0402]  114.05 31.67 180 top
R215  4.7K/NC  [SR0402]  114.05 37.9 180 top
R218  4.7K  [SR0402]  42.23 86.44 90 top
R219  4.7K  [SR0402]  26 86.87 90 top
R220  10K  [SR0402]  12.14 79.76 90 top
R226  33  [SR0402]  82.42 66.85 0 top
R229  4.7K  [SR0402]  64.14 94.87 180 top
R242  4.7K  [SR0402]  118.11 19.81 270 top
R243  4.7K  [SR0402]  123.32 30.28 0 bottom
R267  2.2K  [SR0402]  125.22 24.82 180 bottom
R268  2.2K  [SR0402]  129.03 22.91 0 bottom
R269  2.2K  [SR0402]  129.67 27.48 90 bottom
R270  2.2K/NC  [SR0402]  123.32 27.48 90 bottom
R271  2.2K  [SR0402]  125.86 22.28 270 bottom
R272  75  [SR0805]  35.14 93.31 90 bottom
R302  10  [SR0402]  109.47 17.32 180 top
S9  NC  [TSW4-RG-C]  95.38 11.2 0 top
S10  TMG_533_T_R  [SPSW6-T]  76.33 79.88 90 bottom
T2  H1102T  [STFM16-50-285]  33.39 90.96 0 top
U1  SY8089A_ETA3409  [SOT23_5]  59.94 17.02 180 top
U2  HI3136V100  [MLF48B-040-0606L]  87.88 68.12 0 top
U3  H5TQ4G63MFR_PBC_A  [BGA96-32-1609I]  38.99 57.84 180 top
U4  CS0806U  [SOT23A-6L]  56.04 94.14 270 top
U5  DIO2103_SGM8903  [SGM8903]  69.39 92.05 270 top
U6  H5TQ4G63MFR_PBC_A  [BGA96-32-1609I]  38.99 41.43 180 top
U7  -  [RL_8188EUS]  113.82 47.75 270 top
U8  CS0806S  [DFN2510P10E]  51.63 95.35 0 top
U9  GP1FAV50TK0F  [LASER3-1214]  82.52 102.61 180 top
U10  HI3796MV100  [PBGA573-32-27X27]  61.98 53.14 270 top
U11  SY8032  [SOT23_6]  96.39 57.95 180 top
U12  AZ1117-ADJ  [TO-252]  77.54 78.99 270 top
U13  SY8032  [SOT23_6]  69.19 24.38 180 top
U14  LM1117-ADJ  [SOT223A]  133.73 91.95 180 top
U15  SY8089A_ETA3409  [SOT23_5]  36.7 72.44 90 top
U16  ETA6010  [SOT23-5]  21.85 49.71 0 top
U17  MP8126  [TSSOP16EP]  115.93 65.27 0 top
U18  MP1470_1471A  [SOT23_6]  27.69 74.16 180 top
U19  NC  [SOP48-20-720B]  101.35 33.45 90 top
U22  EMMC  [BGA169-20-1428-A]  101.35 33.45 0 top
U23  CS0806S  [DFN2510P10E]  48.46 95.35 0 top
U24  SN74HC125DR  [SOP14-50-150]  125.87 24.81 0 top
U26  ETA6010  [SOT23-5]  14.67 78.74 180 top
U27  /NC  [RN8-0402]  42.29 83.69 90 top
U34  AV2012  [QFN28B-040-0404LH]  109.28 92.91 180 top
UNK#REFDES  -  []  -185.17 -104.52 0 top
X1  24MHZ  [SX2-1205]  98.68 69.39 90 top
X2  24MHZ  [X288]  81.79 41.33 90 top
X4  27MHZ  [SX2-1205]  108.72 82.87 0 top

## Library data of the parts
C1 = SC1210
C2 C4 C20 C25-C27 C29 C44 C59 C63 C65 C114 C171 C315 C319 C347 C348 C353 = SC0805
C3 C5 C7 C8 C10-C14 C16-C19 C24 C30 C34 C36-C43 C45-C56 C58 C60-C62 C64 C67-C70 C73-C89 C92-C104 C106-C110 C112 C113 C115 C117 C119 C121-C132 C135-C155 C157-C159 C163 C166 C170 C172 C174-C178 C182 C185 C186 C188-C190 C193-C195 C197-C199 C203 C206-C208 C211-C223 C226-C230 C232 C233 C237-C241 C243 C245 C258 C264 C270 C271 C282 C283 C287-C289 C297 C303-C308 C310 C313 C314 C316 C317 C323 C324 C334 C336 C339 C341-C344 C354 C364 C365 C414 C489-C491 C531 C532 C534-C538 C545 D4 D5 D10 D15 = SC0402
C6 C21 C35 C71 C72 C90 C91 C111 C116 C133 C168 C169 C173 C179-C181 C187 C191 C192 C196 C200-C202 C204 C205 C209 C210 C225 C246 C257 C281 C320 C350 C351 C363 C487 = SC0603
C9 C15 C22 C28 C31-C33 C57 C118 C120 C242 C248 C250 C251 C255 = HSC0402
C23 C105 C183 C244 = SC1206
C66 C160-C162 C165 C184 C296 = SAC6666
C134 C167 = SCAPC2-0606
C164 = SC0402: signal model: SC0402_10PF/NC
D3 = SEN3-100C
D6 D9 Q1-Q9 Q13-Q15 = SOT23
D7 D8 D11 D17 = SD1714A
D12-D14 D27 = HSOD323A
ID1-ID6 = ID-BOARD
J1 = SIP-6P-100
J3-J5 = SIP-1P
J6 J9 = USB4-1415
J7 = HEAD0212-RF-SUB
J10 = PWC0103-M-N
J12 = USB3_0_9P_DIP_MAINSUPER
J13 = SDC10-1415
J14 = HEAD0202-RF
J16 = JTDA18250
J18 = WBC0104-49T
J25 = MJ8-RLY
J26 = WBC0119-20R-A
J34 = VAF6-1107
L1 L6 L16 LB1 LB7 LB8 LB11 LB12 LB17 LB18 LB20-LB22 LB31 LB35 = SL0402
L2-L5 = SWPA4030S
L7 = L6X6X4_5
L8 = SWPA5040S
L9 = SWPA4020S
L21 = HSL1007
LB3-LB5 LB10 LB13 LB15 LB47 LB49 = SL0805
LB6 LB9 = SL1210
LB14 LB33 = SL0603
LED1 = LED3C-100C
M20-M23 = HOLE138-8STAR
R1 R3-R18 R20-R26 R30-R34 R39-R44 R47-R50 R52 R53 R55-R57 R59-R73 R75 R78-R80 R82-R96 R99-R104 R106-R108 R112 R113 R115 R117 R118 R120-R127 R129-R131 R138 R139 R142 R145-R148 R151-R156 R158-R161 R163 R166 R168 R172-R174 R176 R177 R183-R190 R193 R194 R202 R203 R212 R218-R220 R226 R229 R242 R243 R267-R271 R302 = SR0402
R2 R19 R27 R28 R35 R51 R76 R77 R97 R105 R110 R111 R114 R116 R141 R149 R175 R179 R191 R210 = SR0603
R29 R178 = SR0402: signal model: SR0402_75
R36-R38 R45 R46 = SR0402: signal model: SR0402_33
R54 = SR0402: signal model: SR0402_240
R58 R98 R135 R136 R140 = SR0402: signal model: SR0402_10K
R74 R119 = HSR0402
R109 = SR1206
R144 R215 = SR0402: signal model: SR0402_4.7K
R180-R182 R272 = SR0805
S9 = TSW4-RG-C
S10 = SPSW6-T
T2 = STFM16-50-285
U1 U15 = SOT23_5
U2 = MLF48B-040-0606L
U3 U6 = BGA96-32-1609I
U4 = SOT23A-6L
U5 = SGM8903
U7 = RL_8188EUS
U8 U23 = DFN2510P10E
U9 = LASER3-1214
U10 = PBGA573-32-27X27
U11 U13 U18 = SOT23_6
U12 = TO-252
U14 = SOT223A
U16 U26 = SOT23-5
U17 = TSSOP16EP
U19 = SOP48-20-720B
U22 = BGA169-20-1428-A
U24 = SOP14-50-150
U27 = RN8-0402
U34 = QFN28B-040-0404LH
X1 X4 = SX2-1205
X2 = X288

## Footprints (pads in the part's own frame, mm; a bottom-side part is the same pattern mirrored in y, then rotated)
BGA96-32-1609I
  round 0.356 smd: A1(-6,-3.2) A2(-6,-2.4) A3(-6,-1.6) A7(-6,1.6) A8(-6,2.4) A9(-6,3.2) B1(-5.2,-3.2) B2(-5.2,-2.4) B3(-5.2,-1.6) B7(-5.2,1.6) B8(-5.2,2.4) B9(-5.2,3.2) C1(-4.4,-3.2) C2(-4.4,-2.4) C3(-4.4,-1.6) C7(-4.4,1.6) C8(-4.4,2.4) C9(-4.4,3.2) D1(-3.6,-3.2) D2(-3.6,-2.4) D3(-3.6,-1.6) D7(-3.6,1.6) D8(-3.6,2.4) D9(-3.6,3.2) E1(-2.8,-3.2) E2(-2.8,-2.4) E3(-2.8,-1.6) E7(-2.8,1.6) E8(-2.8,2.4) E9(-2.8,3.2) F1(-2,-3.2) F2(-2,-2.4) F3(-2,-1.6) F7(-2,1.6) F8(-2,2.4) F9(-2,3.2) G1(-1.2,-3.2) G2(-1.2,-2.4) G3(-1.2,-1.6) G7(-1.2,1.6) G8(-1.2,2.4) G9(-1.2,3.2) H1(-0.4,-3.2) H2(-0.4,-2.4) H3(-0.4,-1.6) H7(-0.4,1.6) H8(-0.4,2.4) H9(-0.4,3.2) J1(0.4,-3.2) J2(0.4,-2.4) J3(0.4,-1.6) J7(0.4,1.6) J8(0.4,2.4) J9(0.4,3.2) K1(1.2,-3.2) K2(1.2,-2.4) K3(1.2,-1.6) K7(1.2,1.6) K8(1.2,2.4) K9(1.2,3.2) L1(2,-3.2) L2(2,-2.4) L3(2,-1.6) L7(2,1.6) L8(2,2.4) L9(2,3.2) M1(2.8,-3.2) M2(2.8,-2.4) M3(2.8,-1.6) M7(2.8,1.6) M8(2.8,2.4) M9(2.8,3.2) N1(3.6,-3.2) N2(3.6,-2.4) N3(3.6,-1.6) N7(3.6,1.6) N8(3.6,2.4) N9(3.6,3.2) P1(4.4,-3.2) P2(4.4,-2.4) P3(4.4,-1.6) P7(4.4,1.6) P8(4.4,2.4) P9(4.4,3.2) R1(5.2,-3.2) R2(5.2,-2.4) R3(5.2,-1.6) R7(5.2,1.6) R8(5.2,2.4) R9(5.2,3.2) T1(6,-3.2) T2(6,-2.4) T3(6,-1.6) T7(6,1.6) T8(6,2.4) T9(6,3.2)
BGA169-20-1428-A
  round 1.016 smd: 1(-10.16,8.509) 2(10.16,-8.509)
  round 0.254 smd: A4(-6.75,-1.75) A6(-6.75,-0.75) A9(-6.75,0.75) A11(-6.75,1.75) AA1(3.25,-3.25) AA2(3.25,-2.75) AA3(3.25,-2.25) AA4(3.25,-1.75) AA5(3.25,-1.25) AA6(3.25,-0.75) AA7(3.25,-0.25) AA8(3.25,0.25) AA9(3.25,0.75) AA10(3.25,1.25) AA11(3.25,1.75) AA12(3.25,2.25) AA13(3.25,2.75) AA14(3.25,3.25) AE1(5.25,-3.25) AE14(5.25,3.25) AG2(6.25,-2.75) AG13(6.25,2.75) AH4(6.75,-1.75) AH6(6.75,-0.75) AH9(6.75,0.75) AH11(6.75,1.75) B2(-6.25,-2.75) B13(-6.25,2.75) D1(-5.25,-3.25) D14(-5.25,3.25) H1(-3.25,-3.25) H2(-3.25,-2.75) H3(-3.25,-2.25) H4(-3.25,-1.75) H5(-3.25,-1.25) H6(-3.25,-0.75) H7(-3.25,-0.25) H8(-3.25,0.25) H9(-3.25,0.75) H10(-3.25,1.25) H11(-3.25,1.75) H12(-3.25,2.25) H13(-3.25,2.75) H14(-3.25,3.25) J1(-2.75,-3.25) J2(-2.75,-2.75) J3(-2.75,-2.25) J4(-2.75,-1.75) J5(-2.75,-1.25) J6(-2.75,-0.75) J7(-2.75,-0.25) J8(-2.75,0.25) J9(-2.75,0.75) J10(-2.75,1.25) J11(-2.75,1.75) J12(-2.75,2.25) J13(-2.75,2.75) J14(-2.75,3.25) K1(-2.25,-3.25) K2(-2.25,-2.75) K3(-2.25,-2.25) K4(-2.25,-1.75) K5(-2.25,-1.25) K6(-2.25,-0.75) K7(-2.25,-0.25) K8(-2.25,0.25) K9(-2.25,0.75) K10(-2.25,1.25) K11(-2.25,1.75) K12(-2.25,2.25) K13(-2.25,2.75) K14(-2.25,3.25) L1(-1.75,-3.25) L2(-1.75,-2.75) L3(-1.75,-2.25) L4(-1.75,-1.75) L12(-1.75,2.25) L13(-1.75,2.75) L14(-1.75,3.25) M1(-1.25,-3.25) M2(-1.25,-2.75) M3(-1.25,-2.25) M5(-1.25,-1.25) M6(-1.25,-0.75) M7(-1.25,-0.25) M8(-1.25,0.25) M9(-1.25,0.75) M10(-1.25,1.25) M12(-1.25,2.25) M13(-1.25,2.75) M14(-1.25,3.25) N1(-0.75,-3.25) N2(-0.75,-2.75) N3(-0.75,-2.25) N5(-0.75,-1.25) N10(-0.75,1.25) N12(-0.75,2.25) N13(-0.75,2.75) N14(-0.75,3.25) P1(-0.25,-3.25) P2(-0.25,-2.75) P3(-0.25,-2.25) P5(-0.25,-1.25) P10(-0.25,1.25) P12(-0.25,2.25) P13(-0.25,2.75) P14(-0.25,3.25) R1(0.25,-3.25) R2(0.25,-2.75) R3(0.25,-2.25) R5(0.25,-1.25) R10(0.25,1.25) R12(0.25,2.25) R13(0.25,2.75) R14(0.25,3.25) T1(0.75,-3.25) T2(0.75,-2.75) T3(0.75,-2.25) T5(0.75,-1.25) T10(0.75,1.25) T12(0.75,2.25) T13(0.75,2.75) T14(0.75,3.25) U1(1.25,-3.25) U2(1.25,-2.75) U3(1.25,-2.25) U5(1.25,-1.25) U6(1.25,-0.75) U7(1.25,-0.25) U8(1.25,0.25) U9(1.25,0.75) U10(1.25,1.25) U12(1.25,2.25) U13(1.25,2.75) U14(1.25,3.25) V1(1.75,-3.25) V2(1.75,-2.75) V3(1.75,-2.25) V12(1.75,2.25) V13(1.75,2.75) V14(1.75,3.25) W1(2.25,-3.25) W2(2.25,-2.75) W3(2.25,-2.25) W4(2.25,-1.75) W5(2.25,-1.25) W6(2.25,-0.75) W7(2.25,-0.25) W8(2.25,0.25) W9(2.25,0.75) W10(2.25,1.25) W11(2.25,1.75) W12(2.25,2.25) W13(2.25,2.75) W14(2.25,3.25) Y1(2.75,-3.25) Y2(2.75,-2.75) Y3(2.75,-2.25) Y4(2.75,-1.75) Y5(2.75,-1.25) Y6(2.75,-0.75) Y7(2.75,-0.25) Y8(2.75,0.25) Y9(2.75,0.75) Y10(2.75,1.25) Y11(2.75,1.75) Y12(2.75,2.25) Y13(2.75,2.75) Y14(2.75,3.25)
DFN2510P10E
  oval 0.254x0.813 smd: 1(-1,-0.525) 5(1,-0.525) 6(1,0.525) 10(-1,0.525)
  oval 0.229x0.813 smd: 2(-0.5,-0.525) 4(0.5,-0.525) 7(0.5,0.525) 9(-0.5,0.525)
  oval 0.356x0.813 smd: 3(0,-0.525) 8(0,0.525)
HEAD0202-RF
  rect 1.524x1.524 hole 1.016: 1(-1.27,1.27)
  round 1.524 hole 1.016: 2(-1.27,-1.27) 3(1.27,1.27) 4(1.27,-1.27)
HEAD0212-RF-SUB
  rect 1.524x1.524 hole 1.016: 1(-13.97,1.27)
  round 1.524 hole 1.016: 2(-13.97,-1.27) 3(-11.43,1.27) 4(-11.43,-1.27) 5(-8.89,1.27) 6(-8.89,-1.27) 7(-6.35,1.27) 8(-6.35,-1.27) 9(-3.81,1.27) 10(-3.81,-1.27) 11(-1.27,1.27) 12(-1.27,-1.27) 13(1.27,1.27) 14(1.27,-1.27) 15(3.81,1.27) 16(3.81,-1.27) 17(6.35,1.27) 18(6.35,-1.27) 19(8.89,1.27) 20(8.89,-1.27) 21(11.43,1.27) 22(11.43,-1.27) 23(13.97,1.27) 24(13.97,-1.27)
HOLE138-8STAR
  round 3.505 hole 3.505 unplated: (0,0)
  round 0.711 hole 0.305: 1(-3.131,0) 2(-2.214,-2.214) 3(0,-3.131) 4(2.214,-2.214) 5(3.131,0) 6(2.214,2.214) 7(0,3.131) 8(-2.214,2.214)
HOLE138-8STAR#2
  round 3.505 hole 3.505 unplated: (0,0)
  round 0.711 hole 0.305: 1(2.135,2.347) 2(3.023,0.965) 3(3.1,-0.675) 4(2.347,-2.135) 5(0.965,-3.023) 6(-0.675,-3.1) 7(-2.135,-2.347) 8(-3.023,-0.965)
HSC0402
  rect 0.508x0.508 smd: 1(-0.406,0) 2(0.406,0)
HSL1007
  rect 0.914x1.626 smd: 1(-1.1,0) 2(1.1,0)
HSOD323A
  rect 1.118x0.508 smd: 1(1.372,0) 2(-1.372,0)
HSR0402
  rect 0.508x0.508 smd: 1(-0.406,0) 2(0.406,0)
ID-BOARD
  round 1.016 smd: 1(0,0)
JTDA18250
  oval 1.778x2.54 hole 1.016x1.778: 1(-11.17,-7.5) 2(-11.17,7.5)
  oval 1.778x5.08 hole 1.27x4.572: 3(-14.87,7.5) 4(-14.87,-7.5)
  oval 3.302x1.778 hole 2.54x1.016: 5(-9.25,-13.675) 6(9.25,-13.675) 7(9.25,13.675) 8(-9.25,13.675)
L6X6X4_5
  rect 1.651x5.715 smd: 1(-2.3,0) 2(2.3,0)
LASER3-1214
  round 2.032 hole 2.032 unplated: (-4.6,2.1) (0,-3.9) (4.6,2.1)
  rect 1.397x1.397 hole 0.813: 1(-2.54,0)
  round 1.397 hole 0.813: 2(0,0) 3(2.54,0)
LED3C-100C
  rect 1.524x1.524 hole 0.965: 1(0,0)
  round 1.524 hole 0.965: 2(2.54,0) 3(5.08,0)
MJ8-RLY
  round 3.429 hole 3.429 unplated: (-2.794,2.54) (9.906,2.54)
  round 1.27 hole 0.914: 1(0,0) 2(1.016,-1.778) 3(2.032,0) 4(3.048,-1.778) 5(4.064,0) 6(5.08,-1.778) 7(6.096,0) 8(7.112,-1.778) 9(-3.302,-6.604) 10(-1.016,-6.604) 11(8.128,-6.604) 12(10.414,-6.604)
MLF48B-040-0606L
  rect 0.203x0.61 smd: 1(-2.2,-2.879) 2(-1.8,-2.879) 3(-1.4,-2.879) 4(-1,-2.879) 5(-0.6,-2.879) 6(-0.2,-2.879) 7(0.2,-2.879) 8(0.6,-2.879) 9(1,-2.879) 10(1.4,-2.879) 11(1.8,-2.879) 12(2.2,-2.879) 25(2.2,2.879) 26(1.8,2.879) 27(1.4,2.879) 28(1,2.879) 29(0.6,2.879) 30(0.2,2.879) 31(-0.2,2.879) 32(-0.6,2.879) 33(-1,2.879) 34(-1.4,2.879) 35(-1.8,2.879) 36(-2.2,2.879)
  rect 0.61x0.203 smd: 13(2.879,-2.2) 14(2.879,-1.8) 15(2.879,-1.4) 16(2.879,-1) 17(2.879,-0.6) 18(2.879,-0.2) 19(2.879,0.2) 20(2.879,0.6) 21(2.879,1) 22(2.879,1.4) 23(2.879,1.8) 24(2.879,2.2) 37(-2.879,2.2) 38(-2.879,1.8) 39(-2.879,1.4) 40(-2.879,1) 41(-2.879,0.6) 42(-2.879,0.2) 43(-2.879,-0.2) 44(-2.879,-0.6) 45(-2.879,-1) 46(-2.879,-1.4) 47(-2.879,-1.8) 48(-2.879,-2.2)
  rect 3.683x3.683 smd: 49(0,0)
PBGA573-32-27X27
  round 0.356 smd: A1(-10.8,-10.8) A2(-10.8,-10) A3(-10.8,-9.2) A6(-10.8,-6.8) A8(-10.8,-5.2) A10(-10.8,-3.6) A13(-10.8,-1.2) A14(-10.8,-0.4) A16(-10.8,1.2) A18(-10.8,2.8) A20(-10.8,4.4) A22(-10.8,6) A25(-10.8,8.4) A27(-10.8,10) A28(-10.8,10.8) AA1(5.2,-10.8) AA2(5.2,-10) AA3(5.2,-9.2) AA4(5.2,-8.4) AA5(5.2,-7.6) AA6(5.2,-6.8) AA7(5.2,-6) AA18(5.2,2.8) AA19(5.2,3.6) AA20(5.2,4.4) AA21(5.2,5.2) AA24(5.2,7.6) AA25(5.2,8.4) AA26(5.2,9.2) AB1(6,-10.8) AB2(6,-10) AB3(6,-9.2) AB4(6,-8.4) AB5(6,-7.6) AB6(6,-6.8) AB7(6,-6) AB8(6,-5.2) AB9(6,-4.4) AB10(6,-3.6) AB11(6,-2.8) AB12(6,-2) AB13(6,-1.2) AB14(6,-0.4) AB15(6,0.4) AB16(6,1.2) AB24(6,7.6) AB25(6,8.4) AB26(6,9.2) AB27(6,10) AB28(6,10.8) AC2(6.8,-10) AC3(6.8,-9.2) AC4(6.8,-8.4) AC5(6.8,-7.6) AC6(6.8,-6.8) AC7(6.8,-6) AC8(6.8,-5.2) AC9(6.8,-4.4) AC10(6.8,-3.6) AC11(6.8,-2.8) AC12(6.8,-2) AC13(6.8,-1.2) AC14(6.8,-0.4) AC15(6.8,0.4) AC16(6.8,1.2) AC17(6.8,2) AC24(6.8,7.6) AC25(6.8,8.4) AC26(6.8,9.2) AD1(7.6,-10.8) AD2(7.6,-10) AD3(7.6,-9.2) AD4(7.6,-8.4) AD5(7.6,-7.6) AD6(7.6,-6.8) AD7(7.6,-6) AD8(7.6,-5.2) AD9(7.6,-4.4) AD10(7.6,-3.6) AD11(7.6,-2.8) AD12(7.6,-2) AD13(7.6,-1.2) AD14(7.6,-0.4) AD15(7.6,0.4) AD16(7.6,1.2) AD17(7.6,2) AD18(7.6,2.8) AD19(7.6,3.6) AD20(7.6,4.4) AD21(7.6,5.2) AD22(7.6,6) AD23(7.6,6.8) AD24(7.6,7.6) AD25(7.6,8.4) AD26(7.6,9.2) AD27(7.6,10) AD28(7.6,10.8) AE1(8.4,-10.8) AE2(8.4,-10) AE3(8.4,-9.2) AE4(8.4,-8.4) AE5(8.4,-7.6) AE6(8.4,-6.8) AE7(8.4,-6) AE8(8.4,-5.2) AE9(8.4,-4.4) AE10(8.4,-3.6) AE11(8.4,-2.8) AE12(8.4,-2) AE13(8.4,-1.2) AE14(8.4,-0.4) AE15(8.4,0.4) AE16(8.4,1.2) AE17(8.4,2) AE18(8.4,2.8) AE19(8.4,3.6) AE20(8.4,4.4) AE21(8.4,5.2) AE22(8.4,6) AE23(8.4,6.8) AE24(8.4,7.6) AE25(8.4,8.4) AE26(8.4,9.2) AF1(9.2,-10.8) AF2(9.2,-10) AF3(9.2,-9.2) AF4(9.2,-8.4) AF5(9.2,-7.6) AF6(9.2,-6.8) AF7(9.2,-6) AF8(9.2,-5.2) AF9(9.2,-4.4) AF10(9.2,-3.6) AF11(9.2,-2.8) AF12(9.2,-2) AF13(9.2,-1.2) AF14(9.2,-0.4) AF15(9.2,0.4) AF16(9.2,1.2) AF17(9.2,2) AF18(9.2,2.8) AF19(9.2,3.6) AF20(9.2,4.4) AF21(9.2,5.2) AF22(9.2,6) AF23(9.2,6.8) AF24(9.2,7.6) AF25(9.2,8.4) AF26(9.2,9.2) AF27(9.2,10) AF28(9.2,10.8) AG1(10,-10.8) AG2(10,-10) AG3(10,-9.2) AG4(10,-8.4) AG5(10,-7.6) AG6(10,-6.8) AG7(10,-6) AG8(10,-5.2) AG9(10,-4.4) AG10(10,-3.6) AG11(10,-2.8) AG12(10,-2) AG13(10,-1.2) AG14(10,-0.4) AG15(10,0.4) AG16(10,1.2) AG17(10,2) AG19(10,3.6) AG21(10,5.2) AG23(10,6.8) AG24(10,7.6) AG25(10,8.4) AG26(10,9.2) AG27(10,10) AG28(10,10.8) AH1(10.8,-10.8) AH2(10.8,-10) AH3(10.8,-9.2) AH4(10.8,-8.4) AH6(10.8,-6.8) AH7(10.8,-6) AH9(10.8,-4.4) AH10(10.8,-3.6) AH12(10.8,-2) AH13(10.8,-1.2) AH15(10.8,0.4) AH16(10.8,1.2) AH19(10.8,3.6) AH21(10.8,5.2) AH23(10.8,6.8) AH25(10.8,8.4) AH26(10.8,9.2) AH27(10.8,10) AH28(10.8,10.8) B1(-10,-10.8) B2(-10,-10) B3(-10,-9.2) B4(-10,-8.4) B6(-10,-6.8) B8(-10,-5.2) B10(-10,-3.6) B13(-10,-1.2) B14(-10,-0.4) B16(-10,1.2) B18(-10,2.8) B20(-10,4.4) B22(-10,6) B24(-10,7.6) B25(-10,8.4) B26(-10,9.2) B27(-10,10) C1(-9.2,-10.8) C2(-9.2,-10) C3(-9.2,-9.2) C4(-9.2,-8.4) C5(-9.2,-7.6) C6(-9.2,-6.8) C7(-9.2,-6) C8(-9.2,-5.2) C9(-9.2,-4.4) C10(-9.2,-3.6) C11(-9.2,-2.8) C12(-9.2,-2) C13(-9.2,-1.2) C14(-9.2,-0.4) C15(-9.2,0.4) C16(-9.2,1.2) C17(-9.2,2) C18(-9.2,2.8) C19(-9.2,3.6) C20(-9.2,4.4) C21(-9.2,5.2) C22(-9.2,6) C23(-9.2,6.8) C24(-9.2,7.6) C25(-9.2,8.4) C26(-9.2,9.2) C27(-9.2,10) C28(-9.2,10.8) D3(-8.4,-9.2) D4(-8.4,-8.4) D5(-8.4,-7.6) D6(-8.4,-6.8) D7(-8.4,-6) D8(-8.4,-5.2) D9(-8.4,-4.4) D10(-8.4,-3.6) D11(-8.4,-2.8) D12(-8.4,-2) D13(-8.4,-1.2) D14(-8.4,-0.4) D15(-8.4,0.4) D16(-8.4,1.2) D17(-8.4,2) D18(-8.4,2.8) D19(-8.4,3.6) D20(-8.4,4.4) D21(-8.4,5.2) D22(-8.4,6) D23(-8.4,6.8) D24(-8.4,7.6) D25(-8.4,8.4) D26(-8.4,9.2) E1(-7.6,-10.8) E2(-7.6,-10) E3(-7.6,-9.2) E4(-7.6,-8.4) E5(-7.6,-7.6) E6(-7.6,-6.8) E7(-7.6,-6) E8(-7.6,-5.2) E9(-7.6,-4.4) E10(-7.6,-3.6) E11(-7.6,-2.8) E12(-7.6,-2) E13(-7.6,-1.2) E14(-7.6,-0.4) E15(-7.6,0.4) E16(-7.6,1.2) E17(-7.6,2) E18(-7.6,2.8) E19(-7.6,3.6) E20(-7.6,4.4) E21(-7.6,5.2) E22(-7.6,6) E23(-7.6,6.8) E24(-7.6,7.6) E25(-7.6,8.4) E26(-7.6,9.2) E27(-7.6,10) E28(-7.6,10.8) F1(-6.8,-10.8) F2(-6.8,-10) F3(-6.8,-9.2) F4(-6.8,-8.4) F5(-6.8,-7.6) F23(-6.8,6.8) F24(-6.8,7.6) F25(-6.8,8.4) F26(-6.8,9.2) G3(-6,-9.2) G4(-6,-8.4) G5(-6,-7.6) G8(-6,-5.2) G9(-6,-4.4) G11(-6,-2.8) G12(-6,-2) G13(-6,-1.2) G14(-6,-0.4) G16(-6,1.2) G17(-6,2) G18(-6,2.8) G19(-6,3.6) G21(-6,5.2) G24(-6,7.6) G25(-6,8.4) G26(-6,9.2) G27(-6,10) G28(-6,10.8) H1(-5.2,-10.8) H2(-5.2,-10) H3(-5.2,-9.2) H4(-5.2,-8.4) H5(-5.2,-7.6) H11(-5.2,-2.8) H12(-5.2,-2) H13(-5.2,-1.2) H14(-5.2,-0.4) H16(-5.2,1.2) H17(-5.2,2) H18(-5.2,2.8) H21(-5.2,5.2) H22(-5.2,6) H24(-5.2,7.6) H25(-5.2,8.4) H26(-5.2,9.2) J1(-4.4,-10.8) J2(-4.4,-10) J3(-4.4,-9.2) J4(-4.4,-8.4) J5(-4.4,-7.6) J21(-4.4,5.2) J22(-4.4,6) J24(-4.4,7.6) J25(-4.4,8.4) J26(-4.4,9.2) J27(-4.4,10) K3(-3.6,-9.2) K4(-3.6,-8.4) K5(-3.6,-7.6) K11(-3.6,-2.8) K12(-3.6,-2) K13(-3.6,-1.2) K14(-3.6,-0.4) K15(-3.6,0.4) K16(-3.6,1.2) K17(-3.6,2) K18(-3.6,2.8) K19(-3.6,3.6) K21(-3.6,5.2) K22(-3.6,6) K24(-3.6,7.6) K25(-3.6,8.4) K26(-3.6,9.2) K27(-3.6,10) K28(-3.6,10.8) L1(-2.8,-10.8) L2(-2.8,-10) L3(-2.8,-9.2) L4(-2.8,-8.4) L5(-2.8,-7.6) L11(-2.8,-2.8) L12(-2.8,-2) L13(-2.8,-1.2) L14(-2.8,-0.4) L15(-2.8,0.4) L16(-2.8,1.2) L17(-2.8,2) L18(-2.8,2.8) L19(-2.8,3.6) L21(-2.8,5.2) L22(-2.8,6) L24(-2.8,7.6) L25(-2.8,8.4) L26(-2.8,9.2) L27(-2.8,10) L28(-2.8,10.8) M3(-2,-9.2) M4(-2,-8.4) M5(-2,-7.6) M6(-2,-6.8) M11(-2,-2.8) M12(-2,-2) M13(-2,-1.2) M14(-2,-0.4) M15(-2,0.4) M16(-2,1.2) M17(-2,2) M18(-2,2.8) M19(-2,3.6) M21(-2,5.2) M22(-2,6) M24(-2,7.6) M25(-2,8.4) M26(-2,9.2) N1(-1.2,-10.8) N2(-1.2,-10) N3(-1.2,-9.2) N4(-1.2,-8.4) N5(-1.2,-7.6) N6(-1.2,-6.8) N7(-1.2,-6) N9(-1.2,-4.4) N11(-1.2,-2.8) N12(-1.2,-2) N13(-1.2,-1.2) N14(-1.2,-0.4) N15(-1.2,0.4) N16(-1.2,1.2) N17(-1.2,2) N18(-1.2,2.8) N19(-1.2,3.6) N22(-1.2,6) N24(-1.2,7.6) N25(-1.2,8.4) N26(-1.2,9.2) N27(-1.2,10) N28(-1.2,10.8) P2(-0.4,-10) P3(-0.4,-9.2) P4(-0.4,-8.4) P5(-0.4,-7.6) P6(-0.4,-6.8) P7(-0.4,-6) P9(-0.4,-4.4) P11(-0.4,-2.8) P12(-0.4,-2) P13(-0.4,-1.2) P14(-0.4,-0.4) P15(-0.4,0.4) P16(-0.4,1.2) P17(-0.4,2) P18(-0.4,2.8) P19(-0.4,3.6) P22(-0.4,6) P24(-0.4,7.6) P25(-0.4,8.4) P26(-0.4,9.2) R1(0.4,-10.8) R2(0.4,-10) R3(0.4,-9.2) R4(0.4,-8.4) R5(0.4,-7.6) R6(0.4,-6.8) R7(0.4,-6) R9(0.4,-4.4) R11(0.4,-2.8) R12(0.4,-2) R13(0.4,-1.2) R14(0.4,-0.4) R15(0.4,0.4) R16(0.4,1.2) R17(0.4,2) R18(0.4,2.8) R19(0.4,3.6) R21(0.4,5.2) R22(0.4,6) R24(0.4,7.6) R25(0.4,8.4) R26(0.4,9.2) T1(1.2,-10.8) T2(1.2,-10) T3(1.2,-9.2) T4(1.2,-8.4) T5(1.2,-7.6) T6(1.2,-6.8) T7(1.2,-6) T9(1.2,-4.4) T11(1.2,-2.8) T12(1.2,-2) T13(1.2,-1.2) T14(1.2,-0.4) T15(1.2,0.4) T16(1.2,1.2) T17(1.2,2) T18(1.2,2.8) T19(1.2,3.6) T22(1.2,6) T24(1.2,7.6) T25(1.2,8.4) T26(1.2,9.2) T27(1.2,10) T28(1.2,10.8) U2(2,-10) U3(2,-9.2) U4(2,-8.4) U5(2,-7.6) U6(2,-6.8) U7(2,-6) U9(2,-4.4) U11(2,-2.8) U12(2,-2) U13(2,-1.2) U14(2,-0.4) U15(2,0.4) U16(2,1.2) U17(2,2) U18(2,2.8) U19(2,3.6) U21(2,5.2) U22(2,6) U24(2,7.6) U25(2,8.4) U26(2,9.2) V1(2.8,-10.8) V2(2.8,-10) V3(2.8,-9.2) V4(2.8,-8.4) V5(2.8,-7.6) V6(2.8,-6.8) V7(2.8,-6) V9(2.8,-4.4) V11(2.8,-2.8) V12(2.8,-2) V13(2.8,-1.2) V14(2.8,-0.4) V15(2.8,0.4) V16(2.8,1.2) V17(2.8,2) V18(2.8,2.8) V19(2.8,3.6) V21(2.8,5.2) V24(2.8,7.6) V25(2.8,8.4) V26(2.8,9.2) V27(2.8,10) V28(2.8,10.8) W1(3.6,-10.8) W2(3.6,-10) W3(3.6,-9.2) W4(3.6,-8.4) W5(3.6,-7.6) W6(3.6,-6.8) W7(3.6,-6) W9(3.6,-4.4) W21(3.6,5.2) W22(3.6,6) W24(3.6,7.6) W25(3.6,8.4) W26(3.6,9.2) Y2(4.4,-10) Y3(4.4,-9.2) Y4(4.4,-8.4) Y5(4.4,-7.6) Y6(4.4,-6.8) Y7(4.4,-6) Y9(4.4,-4.4) Y10(4.4,-3.6) Y11(4.4,-2.8) Y12(4.4,-2) Y13(4.4,-1.2) Y14(4.4,-0.4) Y15(4.4,0.4) Y18(4.4,2.8) Y19(4.4,3.6) Y21(4.4,5.2) Y22(4.4,6) Y24(4.4,7.6) Y25(4.4,8.4) Y26(4.4,9.2) Y27(4.4,10) Y28(4.4,10.8)
PWC0103-M-N
  rect 2.54x4.572 hole 1.016x3.048: 1(0,0)
  oval 2.54x5.08 hole 1.016x3.429: 2(-6,0)
  oval 4.572x2.54 hole 3.048x1.016: 3(-3.2,4.8)
QFN28B-040-0404LH
  oval 0.203x0.889 smd: 1(-1.2,-1.975) 2(-0.8,-1.975) 3(-0.4,-1.975) 4(0,-1.975) 5(0.4,-1.975) 6(0.8,-1.975) 7(1.2,-1.975) 15(1.2,1.975) 16(0.8,1.975) 17(0.4,1.975) 18(0,1.975) 19(-0.4,1.975) 20(-0.8,1.975) 21(-1.2,1.975)
  oval 0.889x0.203 smd: 8(1.975,-1.2) 9(1.975,-0.8) 10(1.975,-0.4) 11(1.975,0) 12(1.975,0.4) 13(1.975,0.8) 14(1.975,1.2) 22(-1.975,1.2) 23(-1.975,0.8) 24(-1.975,0.4) 25(-1.975,0) 26(-1.975,-0.4) 27(-1.975,-0.8) 28(-1.975,-1.2)
  rect 2.057x2.057 smd: 29(0,0)
RL_8188EUS
  oval 1.016x2.007 hole 0.813: (-5,-0.699) (-3,-0.699) (-1,-0.699) (1,-0.699) (3,-0.699) (5,-0.699)
  round 1.524 hole 0.813: 1(-5,0.699) 2(-3,0.699) 3(-1,0.699) 4(1,0.699) 5(3,0.699) 6(5,0.699)
RN8-0402
  rect 0.305x0.559 smd: 1(-0.762,-0.483) 4(0.762,-0.483) 5(0.762,0.483) 8(-0.762,0.483)
  rect 0.254x0.559 smd: 2(-0.254,-0.483) 3(0.254,-0.483) 6(0.254,0.483) 7(-0.254,0.483)
SAC6666
  rect 3.175x1.016 smd: 1(-2.5,0) 2(2.5,0)
SC0402
  rect 0.508x0.508 smd: 1(-0.406,0) 2(0.406,0)
SC0603
  rect 0.762x0.813 smd: 1(-0.699,0) 2(0.699,0)
SC0805
  rect 0.991x1.27 smd: 1(-0.813,0) 2(0.813,0)
SC1206
  rect 1.295x1.651 smd: 1(-1.346,0) 2(1.346,0)
SC1210
  rect 1.295x2.413 smd: 1(-1.346,0) 2(1.346,0)
SCAPC2-0606
  rect 3.302x1.397 smd: 1(-2.651,0) 2(2.651,0)
SD1714A
  rect 2.286x2.286 smd: 1(-2.286,0) 2(2.286,0)
SDC10-1415
  rect 0.813x1.219 smd: 1(2.9,-5.605) 2(1.8,-5.605) 3(0.7,-5.605) 4(-0.4,-5.605) 5(-1.5,-5.605) 6(-2.6,-5.605) 7(-3.7,-5.605) 8(-4.8,-5.605)
  rect 1.143x1.27 smd: 9(-6.745,-2.975) 10(-6.745,6.025)
  rect 1.524x1.143 smd: 11(-4.94,7.15) 12(2.84,7.15)
  rect 1.143x2.184 smd: 13(7.145,6.355) 15(-7.145,-5.125)
  rect 1.143x2.489 smd: 14(7.145,-4.975)
